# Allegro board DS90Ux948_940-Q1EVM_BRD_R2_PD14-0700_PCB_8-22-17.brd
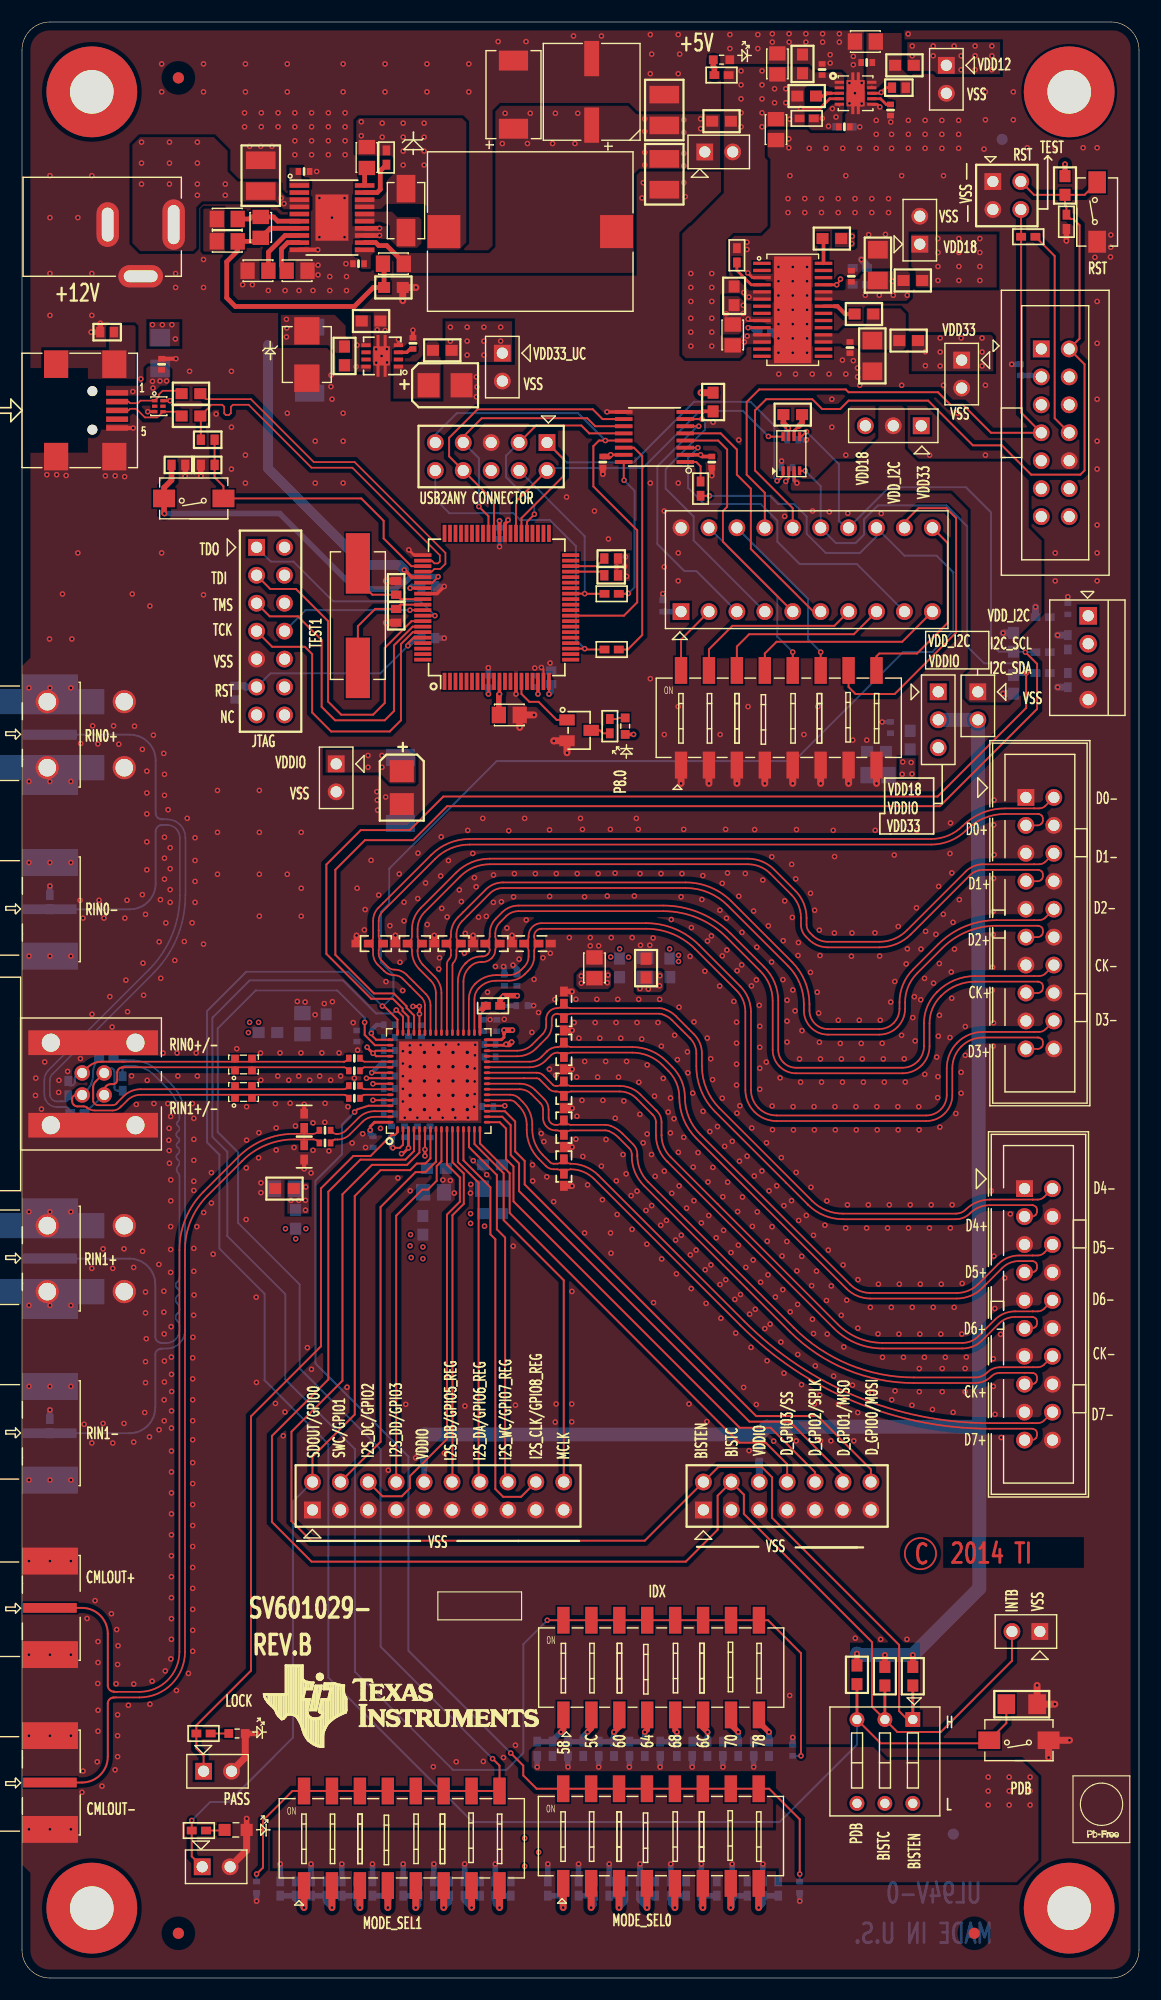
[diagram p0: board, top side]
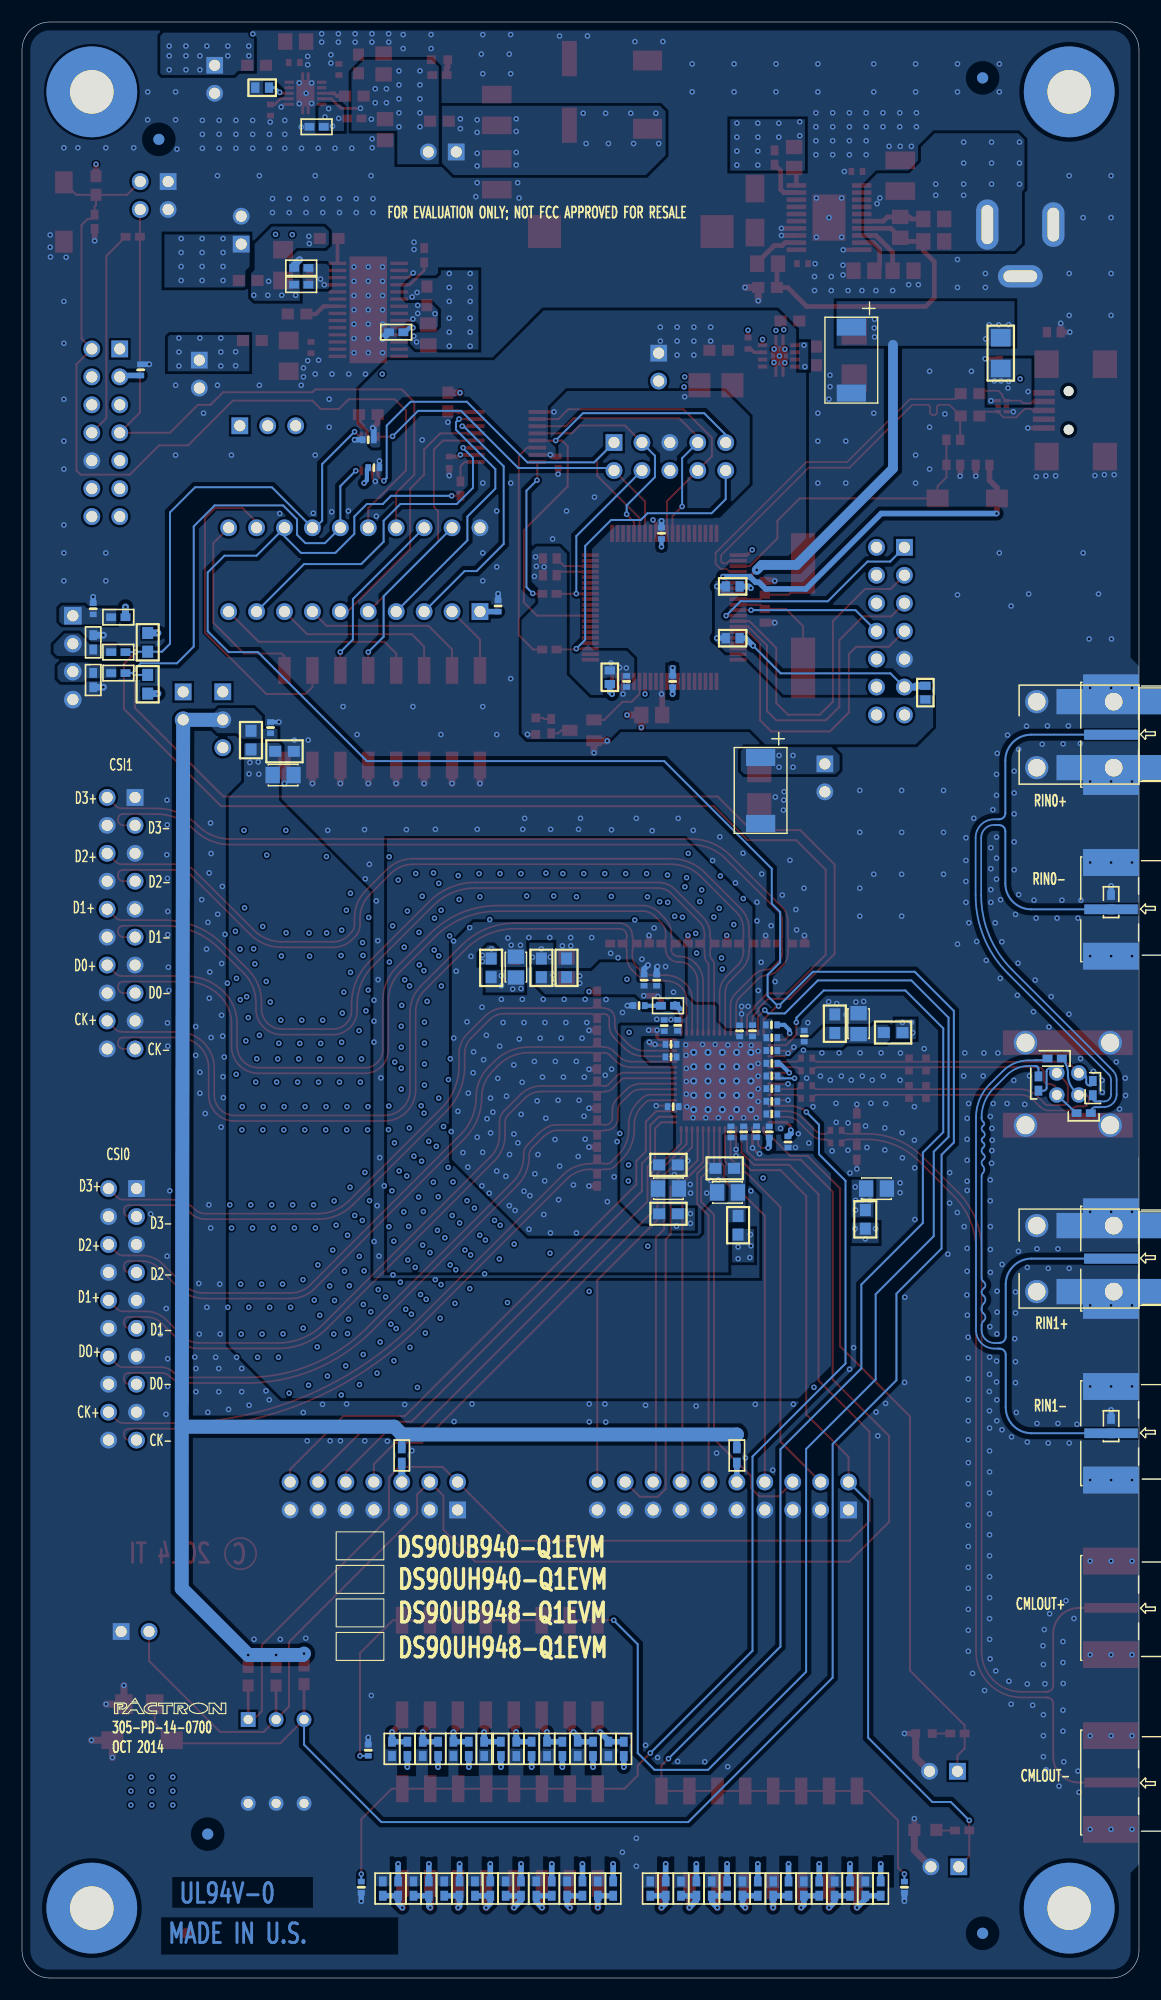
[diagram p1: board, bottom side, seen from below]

Outline 101.6 x 177.8 mm; copper layers: TOP, GND, POWER, BOTTOM. Coordinates in mm from the lower left corner of the outline.
Outline path: 0,175.26 0,2.54 arc(0.74,0.74) 2.54,0 99.06,0 arc(100.86,0.74) 101.6,2.54 101.6,175.26 arc(100.86,177.06) 99.06,177.8 2.54,177.8 arc(0.74,177.06) 0,175.26

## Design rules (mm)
net group DIFFPAIR0: nets N17075556 N17075562
net group DIFFPAIR1: nets RINB+ RINB-
net group DIFFPAIR2: nets RINA+ RINA-
net group DIFFPAIR3: nets N17075712 N17075718
net group DIFFPAIR16: nets N17084985 N17084987
net group DIFFPAIR17: nets N17087573 N17087575
net group DIFFPAIR18: nets DM DP
net group DIFFPAIR19: nets N16849932 N16849953
net group DIFFPAIR20: nets N17103018 N17103031
net group DIFFPAIR21: nets DOUT+ DOUT-

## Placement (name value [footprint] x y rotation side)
C1  0.1uF  [0402_1005_METRIC]  45.47 88.39 180 bottom
C2  0.1uF  [0402_1005_METRIC]  33.43 86.64 180 bottom
C3  0.033uF  [0402_1005_METRIC]  30.23 83.61 0 top
C4  0.033uF  [0402_1005_METRIC]  30.23 82.47 0 top
C5  0.1uF  [0402_1005_METRIC]  33.4 83.14 180 bottom
C6  0.033uF  [0402_1005_METRIC]  30.23 81.11 0 top
C7  0.033uF  [0402_1005_METRIC]  30.23 79.97 0 top
C8  0.1uF  [0402_1005_METRIC]  31.93 76 90 bottom
C9  0.1uF  [0402_1005_METRIC]  27.56 77.06 0 top
C10  0.1uF  [0402_1005_METRIC]  33.63 76.91 270 bottom
C11  0.1uF  [0402_1005_METRIC]  27.56 75.91 0 top
C12  10uF  [1206_3216_METRIC]  90.93 24.89 0 top
C13  2.2uF  [3528-21_EIA]  38.48 144.78 0 top
C14  1uF  [0603_1608_METRIC]  31.75 150.62 0 top
C15  0.01uF  [0402_1005_METRIC]  35.56 148.59 90 top
C16  22uF  [CAP_N]  26.16 147.07 270 bottom
C17  0.1uF  [0402_1005_METRIC]  12.7 146.69 270 top
C18  220PF  [0603]  14.22 137.54 0 top
C19  30pF  [0603]  34.04 123.83 270 top
C20  30pF  [0603]  34.04 126.37 90 top
C21  220PF  [0603]  36.96 126.49 0 bottom
C22  2200PF  [0603]  36.96 121.79 0 bottom
C23  0.1uF  [0402_1005_METRIC]  42.42 117.86 270 bottom
C24  0.1uF  [0402_1005_METRIC]  43.43 131.32 270 bottom
C25  0.1uF  [0402_1005_METRIC]  62.74 137.8 90 top
C26  0.1uF  [0402_1005_METRIC]  52.83 137.8 90 top
C27  0.1uF  [0402_1005_METRIC]  46.61 117.86 270 bottom
C28  4.7uF  [0805_2012_METRIC]  44.32 114.81 0 top
C29  470nF  [0603]  48.13 118.24 90 bottom
C30  0.1uF  [0402_1005_METRIC]  69.6 137.29 0 bottom
C31  0.1uF  [0402_1005_METRIC]  70.1 139.83 180 bottom
C32  0.1uF  [0402_1005_METRIC]  95.12 124.46 90 bottom
C33  4.7pF  [C-0402]  95.12 117.98 270 bottom
C34  4.7pF  [C-0402]  95.12 121.41 90 bottom
C35  0.1uF  [0402_1005_METRIC]  25.65 164.21 0 top
C36  0.022uF  [CAP_HDC-0805_2012_METRIC]  31.37 165.48 90 top
C37  10uF  [1210_3225_METRIC]  21.72 163.83 90 top
C38  100uF  [CAP_7343-31_EIA]  44.7 171.2 90 top
C39  270uF  [CAP_0P327LX0P327W_8P30MMX8P30MM]  51.82 171.45 180 top
C40  100uF  [CAP_HDC-1210_3225_METRIC]  58.42 163.96 270 top
C41  100uF  [CAP_HDC-1210_3225_METRIC]  58.42 169.8 90 top
C42  180pF  [CAP_HDC-0805_2012_METRIC]  21.72 159.13 90 top
C43  150pF  [CAP_HDC-0805_2012_METRIC]  25.02 155.19 0 top
C44  0.01uF  [0402_1005_METRIC]  30.61 155.83 180 top
C45  560pF  [CAP_HDC-0805_2012_METRIC]  18.67 159.89 0 top
C46  4.7uF  [0805_2012_METRIC]  68.71 173.99 90 top
C47  1uF  [0603_1608_METRIC]  70.99 173.99 90 top
C48  0.1uF  [0402_1005_METRIC]  72.77 173.48 90 top
C49  4.7uF  [0805_2012_METRIC]  76.71 176.02 180 top
C50  0.1uF  [0402_1005_METRIC]  76.83 174.12 180 top
C51  0.01uF  [0402_1005_METRIC]  78.99 169.8 270 top
C52  4.7uF  [0805_2012_METRIC]  68.58 168.02 270 top
C53  0.1uF  [0402_1005_METRIC]  74.8 168.28 0 top
C54  10uF  [0805_2012_METRIC]  56.67 91.89 90 bottom
C55  1uF  [0603_1608_METRIC]  56.76 91.8 90 top
C56  0.1uF  [0402_1005_METRIC]  42.57 83.72 180 bottom
C57  0.01uF  [0402_1005_METRIC]  33.4 81.99 0 bottom
C58  0.01uF  [0402_1005_METRIC]  42.57 84.87 180 bottom
C59  10uF  [0805_2012_METRIC]  52.07 91.82 90 top
C60  1uF  [0603_1608_METRIC]  52.07 91.82 90 bottom
C61  0.1uF  [0402_1005_METRIC]  43.87 90.7 90 bottom
C62  0.01uF  [0402_1005_METRIC]  45.02 90.7 90 bottom
C63  4.7uF  [0805_2012_METRIC]  64.64 149.35 90 top
C64  1uF  [0603_1608_METRIC]  64.77 152.91 270 top
C65  0.1uF  [0402_1005_METRIC]  75.44 154.69 270 top
C66  10uF  [1206_3216_METRIC]  77.85 155.7 90 top
C67  10uF  [0805_2012_METRIC]  25.51 86.75 90 bottom
C68  1uF  [0603_1608_METRIC]  27.66 86.75 90 bottom
C69  0.1uF  [0402_1005_METRIC]  30.45 85.62 90 bottom
C70  0.01uF  [0402_1005_METRIC]  33.4 84.3 0 bottom
C71  10uF  [0805_2012_METRIC]  23.88 71.76 180 bottom
C72  1uF  [0603_1608_METRIC]  23.88 71.76 180 top
C73  0.1uF  [0402_1005_METRIC]  33.4 79.7 0 bottom
C74  0.01uF  [0402_1005_METRIC]  33.4 80.85 0 bottom
C75  10uF  [0805_2012_METRIC]  37.44 71.41 0 bottom
C76  1uF  [0603_1608_METRIC]  37.69 73.6 0 bottom
C77  0.1uF  [0402_1005_METRIC]  36.32 86.1 270 bottom
C78  0.01uF  [0402_1005_METRIC]  37.11 76.91 90 bottom
C79  0.1uF  [0402_1005_METRIC]  75.31 148.21 90 top
C80  10uF  [1206_3216_METRIC]  77.34 147.45 270 top
C81  10uF  [0805_2012_METRIC]  42.8 71.76 180 bottom
C82  1uF  [0603_1608_METRIC]  42.8 73.91 180 bottom
C83  0.1uF  [0402_1005_METRIC]  43.19 86.58 90 bottom
C84  0.01uF  [0402_1005_METRIC]  42.37 79.2 180 bottom
C85  0.01uF  [0402_1005_METRIC]  41.97 86.6 90 bottom
C86  0.01uF  [0402_1005_METRIC]  33.4 85.47 0 bottom
C87  0.01uF  [0402_1005_METRIC]  33.4 78.54 0 bottom
C88  22uF  [CAP_N]  34.42 107.95 270 bottom
C89  2.2uF  [3528-21_EIA]  34.54 108.2 270 top
C90  0.1uF  [0402_1005_METRIC]  78.99 113.67 270 bottom
C91  10uF  [0805_2012_METRIC]  77.85 109.35 180 bottom
C92  1uF  [0603_1608_METRIC]  77.72 111.51 180 bottom
C93  0.1uF  [0402_1005_METRIC]  34.79 76.92 90 bottom
C94  0.01uF  [0402_1005_METRIC]  35.96 76.91 90 bottom
C95  0.01uF  [0402_1005_METRIC]  35.15 86.11 270 bottom
C99  0.1uF  [0402_1005_METRIC]  58.29 124.71 270 bottom
C100  0.1uF  [0402_1005_METRIC]  90.81 146.18 270 bottom
C101  2.2nF  [C-0402]  95 159.64 270 top
C102  0.1uF  [0402_1005_METRIC]  70.74 8.26 90 bottom
C103  0.1uF  [0402_1005_METRIC]  21.34 8.26 90 bottom
C104  0.1uF  [0402_1005_METRIC]  70.1 20.7 270 bottom
D1  1SMB5922  [DO-214AA_SMB]  25.91 147.57 90 top
D3  -  [DIODE]  34.92 160.66 270 top
F1  FUSE  [1206]  12.57 147.7 90 bottom
J1  HSD_2X2  [CON_HSD-4P]  -0.13 81.27 90 top
J2  FAKRA  [59S20X-40ML5-Y]  0 113.02 90 bottom
J3  SMA  [EDGE_MOUNT]  0.04 113.02 270 bottom
J4  SMA  [EDGE_MOUNT]  0.04 97.14 270 bottom
J5  SMA  [EDGE_MOUNT]  0.04 33.64 90 top
J6  SMA  [EDGE_MOUNT]  0.04 17.77 90 top
J7  FAKRA  [59S20X-40ML5-Y]  0 65.39 90 bottom
J8  SMA  [EDGE_MOUNT]  0.04 65.39 270 bottom
J9  SMA  [EDGE_MOUNT]  0.04 49.52 270 bottom
J10  mini USB 5pin  [MINI_B_USB_SURFACE_MOUNT]  0 142.49 270 top
J11  HEADER 7X2_open  [0_100INCHX2X7]  21.34 130.05 270 top
J12  HEADER 5X2  [THROUGH_HOLE]  47.75 139.57 180 top
J13  IDC1X4  [IDC-1X4]  96.98 120.02 270 top
J14  HEADER 7X2  [0_100INCHX2X7]  61.98 42.55 0 top
J15  2X10-Pin Header  [N2520_6002RB]  92.58 95.89 270 top
J16  2X10-Pin Header  [N2520_6002RB]  92.46 60.33 270 top
J17  2X10-Pin Header  [HEADER_2X10P]  26.42 42.55 0 top
J18  CONN JACK PWR  [3-TERMINAL_THRU_HOLE_POWER_JACK]  10.79 154.69 180 top
J19  DIP20 SOCKET - MSP430G2403IN20  [DIP-20]  71.37 128.02 0 top
J20  -  [JTAG-14]  93.98 140.46 270 top
J21  2X2-Pin Header  [HEADER_2X2P]  88.31 163.3 270 top
JP1  2-Pin Header_open  [HEADER_2P]  17.79 18.79 0 top
JP2  2-Pin Header_open  [HEADER_2P]  17.66 10.11 0 top
JP3  2-Pin Header_open  [HEADER_2P]  91.31 31.5 180 top
JP4  2-Pin Header  [HEADER_2P]  43.69 146.43 270 top
JP5  3-Pin Header  [HEADER_3P]  79.25 141.1 180 top
JP6  2-Pin Header  [HEADER_2P]  86.94 115.64 270 top
JP7  2-Pin Header  [HEADER_2P]  63.37 165.99 0 top
JP8  2-Pin Header  [HEADER_2P]  84.07 172.59 270 top
JP9  2-Pin Header  [HEADER_2P]  81.66 158.88 90 top
JP10  2-Pin Header  [HEADER_2P]  85.47 145.8 270 top
JP11  2-Pin Header  [HEADER_2P]  28.57 109.09 270 top
JP12  3-Pin Header  [HEADER_3P]  83.34 114.37 270 top
L1  Z = 90 ohm  [L_HDC-0805]  20.15 83.04 0 top
L2  Z = 90 ohm  [L_HDC-0805]  20.15 80.54 0 top
L3  BK1608HS600-T  [L0603]  29.34 147.45 90 top
L4  15uH  [SMD]  46.23 158.75 0 top
L5  FB 1K@100MHz,0603  [L0603_1608_METRIC]  58.93 91.82 270 bottom
L6  FB 120@100MHz,0603  [L0603_1608_METRIC]  54.36 91.82 270 bottom
L7  FB 120@100MHz,0603  [L0603_1608_METRIC]  22.37 85.94 0 bottom
L8  FB 120@100MHz,0603  [L0603_1608_METRIC]  24.89 68.96 90 bottom
L9  FB 120@100MHz,0603  [L0603_1608_METRIC]  36.47 68.43 90 bottom
L10  FB 120@100MHz,0603  [L0603_1608_METRIC]  42.8 69.47 0 bottom
L11  FB 1K@100MHz,0603  [L0603_1608_METRIC]  80.77 112.52 270 bottom
LED1  0603_green_LED  [D-0603]  19.56 22.23 180 top
LED2  0603_orange_LED  [0603_SMT]  19.43 13.46 180 top
LED3  0603_red_LED  [D-0603]  63.63 174.37 180 top
LED4  0603_green_LED  [D-0603]  54.86 113.79 270 top
NOREF  -  []  0 175.26 0 top
NOREF#2  -  [unnamed#2]  95.25 171.45 0 top
NOREF#3  -  []  6.35 6.35 0 top
NOREF#4  -  []  2.54 0 0 top
NOREF#5  -  [unnamed#2]  86.61 4.06 0 top
NOREF#6  -  []  101.6 175.26 0 top
NOREF#7  -  [unnamed#2]  14.22 172.72 0 top
NOREF#8  -  []  0 2.54 0 top
NOREF#9  -  [unnamed#2]  14.22 4.06 0 top
NOREF#10  -  []  2.54 177.8 0 top
NOREF#11  -  []  6.35 171.45 0 top
NOREF#12  -  []  95.25 6.35 0 top
NOREF#13  -  []  95.25 171.45 0 top
NOREF#14  -  []  95.25 6.35 0 top
NOREF#15  -  []  99.06 0 0 top
NOREF#16  -  [unnamed#2]  6.35 6.35 0 top
NOREF#17  -  []  6.35 6.35 0 top
NOREF#18  -  []  6.35 171.45 0 top
NOREF#19  -  [unnamed#2]  95.25 6.35 0 top
NOREF#20  -  []  101.6 2.54 0 top
NOREF#21  -  []  95.25 171.45 0 top
NOREF#22  -  [unnamed#2]  6.35 171.45 0 top
NOREF#23  -  []  99.06 177.8 0 top
NOREF#24  -  [unnamed#2]  14.22 4.06 180 bottom
NOREF#25  -  [unnamed#2]  89.15 167.13 180 bottom
NOREF#26  -  [unnamed#2]  84.71 13.08 180 bottom
NOREF#27  -  [unnamed#2]  14.22 172.72 180 bottom
Q1  BSS138  [SOT23]  50.67 113.41 270 top
R1  220 Ohm,0402  [RES_HDC-0402]  16.51 22.23 180 top
R2  220 Ohm,0402  [RES_HDC-0402]  16.09 13.41 180 top
R3  0 Ohm,0402_open  [RES_HDC-0402]  42.84 88.38 180 top
R4  0 Ohm,0402  [RES_HDC-0402]  42.84 88.38 0 bottom
R5  45.3K Ohm,0402  [RES_HDC-0402]  67.39 8.13 270 bottom
R6  90.9K Ohm,0402  [RES_HDC-0402]  64.59 8.13 270 bottom
R7  107K Ohm,0402  [RES_HDC-0402]  61.8 8.13 270 bottom
R8  113K Ohm,0402  [RES_HDC-0402]  59 8.13 270 bottom
R9  113K Ohm,0402  [RES_HDC-0402]  56.21 8.13 270 bottom
R10  107K Ohm,0402  [RES_HDC-0402]  53.42 8.13 270 bottom
R11  232K Ohm,0402  [RES_HDC-0402]  50.62 8.13 270 bottom
R12  0 Ohm,0402_open  [RES_HDC-0402]  47.83 8.13 270 bottom
R13  45.3K Ohm,0402  [RES_HDC-0402]  43.05 8.13 270 bottom
R14  90.9K Ohm,0402  [RES_HDC-0402]  40.26 8.13 270 bottom
R15  107K Ohm,0402  [RES_HDC-0402]  37.46 8.13 270 bottom
R16  113K Ohm,0402  [RES_HDC-0402]  34.67 8.13 270 bottom
R17  113K Ohm,0402  [RES_HDC-0402]  31.88 8.13 270 bottom
R18  107K Ohm,0402  [RES_HDC-0402]  29.08 8.13 270 bottom
R19  232K Ohm,0402  [RES_HDC-0402]  26.29 8.13 270 bottom
R20  0 Ohm,0402_open  [RES_HDC-0402]  23.49 8.13 270 bottom
R21  182K Ohm,0402  [RES_HDC-0402]  68.78 8.13 90 bottom
R22  113K Ohm,0402  [RES_HDC-0402]  65.99 8.13 90 bottom
R23  93.1K Ohm,0402  [RES_HDC-0402]  63.2 8.13 90 bottom
R24  68.1K Ohm,0402  [RES_HDC-0402]  60.4 8.13 90 bottom
R25  47.5K Ohm,0402  [RES_HDC-0402]  57.61 8.13 90 bottom
R26  31.6K Ohm,0402  [RES_HDC-0402]  54.81 8.13 90 bottom
R27  47.5K Ohm,0402  [RES_HDC-0402]  52.02 8.13 90 bottom
R28  40.2K Ohm,0402  [RES_HDC-0402]  49.23 8.13 90 bottom
R29  182K Ohm,0402  [RES_HDC-0402]  44.45 8.13 90 bottom
R30  113K Ohm,0402  [RES_HDC-0402]  41.66 8.13 90 bottom
R31  93.1K Ohm,0402  [RES_HDC-0402]  38.86 8.13 90 bottom
R32  68.1K Ohm,0402  [RES_HDC-0402]  36.07 8.13 90 bottom
R33  47.5K Ohm,0402  [RES_HDC-0402]  33.27 8.13 90 bottom
R34  31.6K Ohm,0402  [RES_HDC-0402]  30.48 8.13 90 bottom
R35  47.5K Ohm,0402  [RES_HDC-0402]  27.69 8.13 90 bottom
R36  40.2K Ohm,0402  [RES_HDC-0402]  24.89 8.13 90 bottom
R37  0 Ohm,0402_open  [RES_HDC-0402]  4.2 80.89 90 bottom
R38  0 Ohm,0402_open  [RES_HDC-0402]  5.03 78.62 0 bottom
R40  45.3K Ohm,0402  [RES_HDC-0402]  66.55 20.83 90 bottom
R41  90.9K Ohm,0402  [RES_HDC-0402]  63.75 20.83 90 bottom
R42  107K Ohm,0402  [RES_HDC-0402]  60.96 20.83 90 bottom
R43  113K Ohm,0402  [RES_HDC-0402]  58.04 20.83 90 bottom
R44  113K Ohm,0402  [RES_HDC-0402]  55.24 20.83 90 bottom
R45  107K Ohm,0402  [RES_HDC-0402]  52.45 20.83 90 bottom
R46  232K Ohm,0402  [RES_HDC-0402]  49.66 20.83 90 bottom
R47  0 Ohm,0402_open  [RES_HDC-0402]  46.86 20.83 90 bottom
R48  49.9ohm,0402_open  [RES_HDC-0402]  25.67 77.92 90 top
R49  49.9ohm,0402_open  [RES_HDC-0402]  25.67 75.05 270 top
R50  49.9ohm,0402_open  [RES_HDC-0402]  2.54 97.79 90 bottom
R52  182K Ohm,0402  [RES_HDC-0402]  67.94 20.83 270 bottom
R53  113K Ohm,0402  [RES_HDC-0402]  65.15 20.83 270 bottom
R54  93.1K Ohm,0402  [RES_HDC-0402]  62.36 20.83 270 bottom
R55  68.1K Ohm,0402  [RES_HDC-0402]  59.56 20.83 270 bottom
R56  47.5K Ohm,0402  [RES_HDC-0402]  56.64 20.83 270 bottom
R57  31.6K Ohm,0402  [RES_HDC-0402]  53.85 20.83 270 bottom
R58  47.5K Ohm,0402  [RES_HDC-0402]  51.05 20.83 270 bottom
R59  40.2K Ohm,0402  [RES_HDC-0402]  48.26 20.83 270 bottom
R60  10K  [RES_HDC-0603]  75.95 27.56 90 top
R61  10K  [RES_HDC-0603]  78.49 27.43 90 top
R62  10K  [RES_HDC-0603]  81.03 27.43 90 top
R63  0 Ohm,0402_open  [RES_HDC-0402]  9.14 81.31 270 bottom
R64  0 Ohm,0402_open  [RES_HDC-0402]  7.67 83.59 180 bottom
R65  49.9ohm,0402_open  [RES_HDC-0402]  2.54 50.17 90 bottom
R66  33 ohm  [RES_0603]  15.37 144.02 0 top
R67  33 ohm  [RES_0603]  15.37 141.99 0 top
R68  0 Ohm, 0603  [R0603_1608_METRIC]  38.23 147.96 180 top
R69  1.5K  [0603]  16.89 139.83 0 top
R70  33K ohm  [0603]  7.75 149.61 180 top
R71  1.2M ohm  [0603]  16.89 137.54 180 top
R72  33K ohm  [0603]  19.43 116.84 270 bottom
R73  0 Ohm,0402_open  [RES_HDC-0402]  53.63 125.82 0 top
R74  0 Ohm,0402_open  [RES_HDC-0402]  53.63 120.76 0 top
R75  220 Ohm,0402  [RES_HDC-0402]  53.47 113.79 270 top
R76  10K  [RES_HDC-0603]  62.86 143.26 90 top
R77  10K  [RES_HDC-0603]  70.1 142.11 0 top
R78  1.5K  [0603]  53.59 127.51 0 top
R79  1.5K  [0603]  53.59 129.03 0 top
R80  100_open  [RES_HDC-0402]  32.19 94.03 0 top
R81  4.7K  [R-0603]  90.17 117.6 90 bottom
R82  4.7K  [R-0603]  90.17 121.41 270 bottom
R83  0 Ohm  [R-0402]  92.84 123.7 180 bottom
R84  0 Ohm  [R-0402]  92.84 118.62 0 bottom
R85  0 Ohm  [R-0402]  92.84 120.52 0 bottom
R86  100_open  [RES_HDC-0402]  35.73 94.03 0 top
R87  0 Ohm,0402_open  [RES_HDC-0402]  67.06 47.5 90 bottom
R88  100_open  [RES_HDC-0402]  39.26 94.03 0 top
R89  100_open  [RES_HDC-0402]  42.8 94.03 0 top
R90  100_open  [RES_HDC-0402]  46.33 94.03 0 top
R91  0 Ohm,0402_open  [RES_HDC-0402]  36.58 47.5 90 bottom
R92  100_open  [RES_HDC-0402]  49.29 87.91 270 top
R93  100_open  [RES_HDC-0402]  49.29 84.37 270 top
R94  100_open  [RES_HDC-0402]  49.29 80.84 270 top
R95  100_open  [RES_HDC-0402]  49.29 77.3 270 top
R96  100_open  [RES_HDC-0402]  49.29 73.77 270 top
R97  0 Ohm,0402  [RES_HDC-0402]  33.15 165.48 270 top
R98  220 Ohm,0402  [RES_HDC-0402]  63.63 172.97 0 top
R99  0 Ohm, 0603  [R0603_1608_METRIC]  63.63 168.78 0 top
R100  52.3Kohm  [RES_HDC-0805_2012_METRIC]  18.67 157.86 180 top
R101  9.53Kohm  [RES_HDC-0805_2012_METRIC]  21.46 155.19 180 top
R102  3.09Kohm  [RES_HDC-0805_2012_METRIC]  33.78 155.83 180 top
R103  0 Ohm, 0603  [R0603_1608_METRIC]  80.26 173.86 0 top
R104  2.49K  [0603]  79.76 171.83 0 top
R105  100K  [RES_HDC-0603]  71.37 171.07 180 top
R106  1K  [RES_HDC-0603]  33.78 153.67 180 top
R107  0 Ohm,0402  [RES_HDC-0402]  71.37 169.04 0 top
R108  4.99K  [0603]  79.76 171.83 180 bottom
R109  0 Ohm,0402_open  [RES_HDC-0402]  74.8 168.28 0 bottom
R110  23.2K  [0402]  76.2 155.45 180 bottom
R111  100K  [RES_HDC-0603]  73.66 158.12 180 top
R112  12.1K  [0402]  76.2 153.92 180 bottom
R113  0 Ohm, 0603  [R0603_1608_METRIC]  81.03 154.31 0 top
R114  100K  [RES_HDC-0603]  76.58 151.26 180 top
R115  0 Ohm,0402  [RES_HDC-0402]  65.02 156.59 270 top
R116  0 Ohm,0402  [RES_HDC-0402]  67.56 149.61 180 bottom
R117  0 Ohm, 0603  [R0603_1608_METRIC]  80.64 148.84 0 top
R118  330ohm  [R-0402]  91.53 158.28 180 top
R119  47Kohm  [R-0603]  94.87 162.94 90 top
R120  0 Ohm,0402_open  [RES_HDC-0402]  61.72 135.38 90 top
S1  SW SMD-8  [SMD-20]  58.12 12.9 0 top
S2  SW SMD-8  [SMD-20]  34.54 12.7 0 top
S3  SW DIP-3  [DIP-6]  78.49 19.69 180 top
S4  SW SMD-8  [SMD-20]  58.14 28.22 0 top
S5  SW SMD-8  [SMD-20]  68.83 114.55 0 top
SW1  SPST  [ADTSM31NV]  90.68 21.61 180 top
SW2  SPST  [ADTSM31NV]  15.62 134.49 180 top
SW3  SPST  [ADTSM31NV]  97.79 160.53 90 top
TP1  TEST POINT  [TEST_POINT]  33.96 94.03 0 top
TP2  TEST POINT  [TEST_POINT]  30.42 94.03 0 top
TP3  TEST POINT  [TEST_POINT]  37.49 94.03 0 top
TP4  TEST POINT  [TEST_POINT]  41.03 94.03 0 top
TP5  TEST POINT  [TEST_POINT]  48.1 94.03 0 top
TP6  TEST POINT  [TEST_POINT]  44.56 94.03 0 top
TP7  TEST POINT  [TEST_POINT]  49.29 79.07 90 top
TP8  TEST POINT  [TEST_POINT]  49.29 82.6 90 top
TP9  TEST POINT  [TEST_POINT]  49.29 75.53 90 top
TP10  TEST POINT  [TEST_POINT]  49.29 86.14 90 top
TP11  TEST POINT  [TEST_POINT]  49.29 72 90 top
TP12  TEST POINT  [TEST_POINT]  49.29 89.67 90 top
U1  DS90UH948Q  [WQFN-64]  37.9 81.54 90 top
U2  TPS73533DRB  [TPS73533DRBT]  32.77 147.45 90 top
U3  TPD4E004DRY  [SON-6]  12.45 142.88 270 top
U4  MSP430F5529IPN  [TQFP-80]  43.18 124.59 0 top
U5  TXB0106IPWR  [16TSSOP]  57.53 140.08 90 top
U6  TCA9406DCUR  [8-VFSOP_0P091_2P30MM_WIDTH]  69.98 138.56 90 top
U7  LM25576MH/NOPB  [20-TSSOP]  28.19 160.02 270 top
U8  TPS74801DRC  [10-VFDFN_EXPOSED_PAD]  75.82 171.32 0 top
U9  TPS767D318PWP  [28-HTSSOP]  70.1 151.64 270 top
Y1  Crystal, SMT Quart Crystal  [0_484X0_190_INCH]  30.55 123.84 270 top

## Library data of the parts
C1 C2 C5 C8 C10 C24 C28 C32 C46 C48-C50 C52-C54 C56 C59 C61 C63 C65 C67 C69 C71 C73 C75 C77 C79 C81 C83 C90 C91 C93 C102-C104 = CAPACITOR NON-POL_12
C3 C4 C6 C7 C9 C11 C17 C23 C25-C27 C30 C31 C35 C99 C100 = CAPACITOR NON-POL_0
C12 C66 C80 = CAPACITOR NON-POL_9
C13 C16 C38 C39 C88 C89 = CAPACITOR POL_1
C14 C47 C55 C60 C64 C68 C72 C76 C82 C92 = CAPACITOR NON-POL_10
C15 C40 C41 C44 C51 C57 C58 C62 C70 C74 C78 C84-C87 C94 C95 = CAPACITOR NON-POL_11
C18 C21 C22 = CAP NP
C19 C20 C29 = C
C33 C34 = CAPACITOR NON-POL_3
C36 C37 C42 C43 C45 = CAPACITOR NON-POL_5
C101 = CAPACITOR NON-POL_7
D1 = DIODE_ZENER
D3 = DIODE_2
F1 = FUSE
J1 = Automotive HSD Connector 2X2_4
J2-J9 = CON5_5
J10 = mini B USB 5pin_5
J11 J14 = HEADER 7X2
J12 = HEADER 5X2
J13 = IDC_1 x 4_2
J15 J16 = JUMPER_14
J17 = JUMPER_1
J18 = CONN JACK PWR
J19 = DIP8 SOCKET_4
J20 = DIP8 SOCKET_5
J21 = JUMPER_20
JP1 JP2 = JUMPER_17
JP3 JP4 JP6-JP11 = JUMPER_0
JP5 JP12 = JUMPER_13
L1 L2 = DLW21S Series_1
L3 = INDUCTOR_1
L4-L11 = INDUCTOR
LED1-LED4 = LED LTST-C230JAKT_2
Q1 = NDS355N/SOT
R1-R38 R40-R50 R52-R59 R63-R65 R73-R75 R87 R91 R97 R98 R107 R109 R115 R116 R120 = R_6
R60-R62 R76 R77 R100-R102 R104-R106 R108 R110-R112 R114 = R_7
R66 R67 R69-R72 R78 R79 = R
R68 R99 R103 R113 R117 = R_1
R80 R86 R88-R90 R92-R96 = 0201 size pads_2
R81 R82 = R_2
R83-R85 = R_3
R118 R119 = ERJ-1GE0R00C_2
S1 S2 S4 S5 = SW SMD-8_1
S3 = SW DIP-8_19
SW1-SW3 = SW PUSHBUTTON-SPST
TP1-TP12 = TEST POINT
U1 = DS90UH928Q_3
U2 = LP3982IMM-ADJ_2
U3 = TPD4E004DRY
U4 = MSP430F5529IPN_0
U5 = CD40109BMS_1
U6 = PCA9306_0
U7 = PKG_20_TSSOP_EP_0
U8 = TPS62052_MSOP_3
U9 = LM2640_SO_8
Y1 = CRYSTAL

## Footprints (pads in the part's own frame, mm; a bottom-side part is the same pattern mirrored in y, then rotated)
0_100INCHX2X7
  rect 1.524x1.524 hole 1.016: 1(0,0)
  round 1.524 hole 1.016: 2(0,2.54) 3(2.54,0) 4(2.54,2.54) 5(5.08,0) 6(5.08,2.54) 7(7.62,0) 8(7.62,2.54) 9(10.16,0) 10(10.16,2.54) 11(12.7,0) 12(12.7,2.54) 13(15.24,0) 14(15.24,2.54)
0_484X0_190_INCH
  rect 5.5x2.2 smd: 1(-4.75,0) 2(4.75,0)
3-TERMINAL_THRU_HOLE_POWER_JACK
  oval 2.032x4.572 hole 1.067x3.556: 1(-3,-4.7)
  oval 2.032x4.064 hole 1.067x3.073: 2(3,-4.7)
  oval 4.064x2.032 hole 3.073x1.067: 3(0,0)
8-VFSOP_0P091_2P30MM_WIDTH
  rect 0.813x0.305 smd: 1(-1.551,0.75) 2(-1.551,0.25) 3(-1.551,-0.25) 4(-1.551,-0.75) 5(1.551,-0.75) 6(1.551,-0.25) 7(1.551,0.25) 8(1.551,0.75)
10-VFDFN_EXPOSED_PAD
  rect 0.85x0.28 smd: 1(-1.475,1) 2(-1.475,0.5) 3(-1.475,0) 4(-1.475,-0.5) 5(-1.475,-1) 6(1.475,-1) 7(1.475,-0.5) 8(1.475,0) 9(1.475,0.5) 10(1.475,1)
  custom 0.412x0.412 smd: 11(0,0)
16TSSOP
  rect 0.35x1.6 smd: 1(-2.275,-2.8) 2(-1.625,-2.8) 3(-0.975,-2.8) 4(-0.325,-2.8) 5(0.325,-2.8) 6(0.975,-2.8) 7(1.625,-2.8) 8(2.275,-2.8) 9(2.275,2.8) 10(1.625,2.8) 11(0.975,2.8) 12(0.325,2.8) 13(-0.325,2.8) 14(-0.975,2.8) 15(-1.625,2.8) 16(-2.275,2.8)
20-TSSOP
  rect 0.42x1.78 smd: 1(-2.925,-2.97) 2(-2.275,-2.97) 3(-1.625,-2.97) 4(-0.975,-2.97) 5(-0.325,-2.97) 6(0.325,-2.97) 7(0.975,-2.97) 8(1.625,-2.97) 9(2.275,-2.97) 10(2.925,-2.97) 11(2.925,2.97) 12(2.275,2.97) 13(1.625,2.97) 14(0.975,2.97) 15(0.325,2.97) 16(-0.325,2.97) 17(-0.975,2.97) 18(-1.625,2.97) 19(-2.275,2.97) 20(-2.925,2.97)
  rect 4.2x3 smd: 21(0,0)
28-HTSSOP
  rect 0.3x1.6 smd: 1(-4.225,-2.8) 2(-3.575,-2.8) 3(-2.925,-2.8) 4(-2.275,-2.8) 5(-1.625,-2.8) 6(-0.975,-2.8) 7(-0.325,-2.8) 8(0.325,-2.8) 9(0.975,-2.8) 10(1.625,-2.8) 11(2.275,-2.8) 12(2.925,-2.8) 13(3.575,-2.8) 14(4.225,-2.8) 15(4.225,2.8) 16(3.575,2.8) 17(2.925,2.8) 18(2.275,2.8) 19(1.625,2.8) 20(0.975,2.8) 21(0.325,2.8) 22(-0.325,2.8) 23(-0.975,2.8) 24(-1.625,2.8) 25(-2.275,2.8) 26(-2.925,2.8) 27(-3.575,2.8) 28(-4.225,2.8)
  rect 9.7x3.4 smd: 29(0,0)
59S20X-40ML5-Y
  rect 0.889x4.877 smd: 1(0,2.538)
  round 2.108 hole 1.6: 2(-3,2.3) 3(3,2.3) 4(3,9.3) 5(-3,9.3)
0402
  rect 0.9x0.7 smd: 1(-0.65,0) 2(0.65,0)
0402_1005_METRIC
  rect 0.508x0.635 smd: 1(-0.508,0) 2(0.508,0)
0603
  rect 0.75x0.95 smd: 1(-0.625,0) 2(0.625,0)
0603_1608_METRIC
  rect 1.1x1 smd: 1(-0.85,0) 2(0.85,0)
0603_SMT
  rect 1.1x1.1 smd: 1(-1,0) 2(1,0)
0805_2012_METRIC
  rect 1.3x1.5 smd: 1(-0.95,0) 2(0.95,0)
1206
  rect 1.6x1.8 smd: 1(-1.4,0) 2(1.4,0)
1206_3216_METRIC
  rect 1.6x1.8 smd: 1(-1.4,0) 2(1.4,0)
1210_3225_METRIC
  rect 1.6x2.7 smd: 1(-1.4,0) 2(1.4,0)
3528-21_EIA
  rect 2x2.2 smd: 1(-1.5,0) 2(1.5,0)
ADTSM31NV
  rect 2x1.6 smd: 1(-2.7,0) 2(2.7,0)
C-0402
  rect 0.9x0.7 smd: 1(-0.65,0) 2(0.65,0)
CAP_0P327LX0P327W_8P30MMX8P30MM
  rect 1.354x3.204 smd: 1(0,3.025) 2(0,-3.025)
CAP_7343-31_EIA
  rect 1.808x2.654 smd: 1(-3.1,0) 2(3.1,0)
CAP_HDC-0805_2012_METRIC
  rect 1.3x1.5 smd: 1(-0.95,0) 2(0.95,0)
CAP_HDC-1210_3225_METRIC
  rect 1.6x2.7 smd: 1(-1.4,0) 2(1.4,0)
CAP_N
  rect 1.554x2.654 smd: 1(-3,0) 2(3,0)
CON_HSD-4P
  round 1.4 hole 0.9: 1(1,-7.6) 2(1,-5.6) 3(-1,-5.6) 4(-1,-7.6)
  rect 2.25x11.8 hole 1.65: 5(-3.75,-10.45) 6(3.75,-10.45)
  round 2.158 hole 1.65: 7(3.75,-2.75) 8(-3.75,-2.75)
D-0603
  rect 0.8x0.8 smd: 1(-0.75,0) 2(0.75,0)
DIODE
  rect 2.5x1.7 smd: 1(-2,0) 2(2,0)
DIP-6
  rect 1.346x1.346 hole 0.838: 1(-2.54,-3.81)
  round 1.346 hole 0.838: 2(0,-3.81) 3(2.54,-3.81) 4(2.54,3.81) 5(0,3.81) 6(-2.54,3.81)
DIP-20
  rect 1.524x1.524 hole 1.016: 1(-11.43,-3.81)
  round 1.524 hole 1.016: 2(-8.89,-3.81) 3(-6.35,-3.81) 4(-3.81,-3.81) 5(-1.27,-3.81) 6(1.27,-3.81) 7(3.81,-3.81) 8(6.35,-3.81) 9(8.89,-3.81) 10(11.43,-3.81) 11(11.43,3.81) 12(8.89,3.81) 13(6.35,3.81) 14(3.81,3.81) 15(1.27,3.81) 16(-1.27,3.81) 17(-3.81,3.81) 18(-6.35,3.81) 19(-8.89,3.81) 20(-11.43,3.81)
DO-214AA_SMB
  rect 2.5x2.3 smd: 1(-2.15,0) 2(2.15,0)
EDGE_MOUNT
  rect 0.889x4.877 smd: 1(0,-2.502)
  rect 2.413x5.08 smd: 2(-4.255,-2.502) 3(4.255,-2.502) 4(4.255,-2.502) 5(-4.255,-2.502)
HEADER_2P
  rect 1.524x1.524 hole 1.016: 1(-1.27,0)
  round 1.524 hole 1.016: 2(1.27,0)
HEADER_2X2P
  rect 1.524x1.524 hole 1.016: 1(0,0)
  round 1.524 hole 1.016: 2(0,2.54) 3(2.54,0) 4(2.54,2.54)
HEADER_2X10P
  rect 1.524x1.524 hole 1.016: 1(0,0)
  round 1.524 hole 1.016: 2(0,2.54) 3(2.54,0) 4(2.54,2.54) 5(5.08,0) 6(5.08,2.54) 7(7.62,0) 8(7.62,2.54) 9(10.16,0) 10(10.16,2.54) 11(12.7,0) 12(12.7,2.54) 13(15.24,0) 14(15.24,2.54) 15(17.78,0) 16(17.78,2.54) 17(20.32,0) 18(20.32,2.54) 19(22.86,0) 20(22.86,2.54)
HEADER_3P
  rect 1.524x1.524 hole 1.016: 1(-2.54,0)
  round 1.524 hole 1.016: 2(0,0) 3(2.54,0)
IDC-1X4
  rect 1.6x1.6 hole 1.016: 1(-3.81,0)
  round 1.6 hole 1.016: 2(-1.27,0) 3(1.27,0) 4(3.81,0)
JTAG-14
  rect 1.524x1.524 hole 1.016: 1(-7.62,-1.27)
  round 1.524 hole 1.016: 2(-7.62,1.27) 3(-5.08,-1.27) 4(-5.08,1.27) 5(-2.54,-1.27) 6(-2.54,1.27) 7(0,-1.27) 8(0,1.27) 9(2.54,-1.27) 10(2.54,1.27) 11(5.08,-1.27) 12(5.08,1.27) 13(7.62,-1.27) 14(7.62,1.27)
L0603
  rect 1.1x1 smd: 1(-0.85,0) 2(0.85,0)
L0603_1608_METRIC
  rect 1.1x1 smd: 1(-0.85,0) 2(0.85,0)
L_HDC-0805
  rect 0.704x0.704 smd: 1(-0.775,-0.552) 2(0.775,-0.552) 3(0.775,0.552) 4(-0.775,0.552)
MINI_B_USB_SURFACE_MOUNT
  round 0.9 hole 0.9 unplated: (-1.75,6.401) (1.75,6.401)
  rect 0.5x2 smd: 1(-1.6,8.651) 2(-0.8,8.651) 3(0,8.651) 4(0.8,8.651) 5(1.6,8.651)
  rect 2.5x2.2 smd: 6(-4.2,8.4) 7(-4.2,3.101) 8(4.2,3.101) 9(4.2,8.4)
N2520_6002RB
  rect 1.524x1.524 hole 1.016: 1(-11.43,-1.27)
  round 1.524 hole 1.016: 2(-11.43,1.27) 3(-8.89,-1.27) 4(-8.89,1.27) 5(-6.35,-1.27) 6(-6.35,1.27) 7(-3.81,-1.27) 8(-3.81,1.27) 9(-1.27,-1.27) 10(-1.27,1.27) 11(1.27,-1.27) 12(1.27,1.27) 13(3.81,-1.27) 14(3.81,1.27) 15(6.35,-1.27) 16(6.35,1.27) 17(8.89,-1.27) 18(8.89,1.27) 19(11.43,-1.27) 20(11.43,1.27)
R0603_1608_METRIC
  rect 1.1x1 smd: 1(-0.85,0) 2(0.85,0)
R-0402
  rect 0.9x0.7 smd: 1(-0.65,0) 2(0.65,0)
R-0603
  rect 1.1x1 smd: 1(-0.85,0) 2(0.85,0)
RES_0603
  rect 1.1x1 smd: 1(-0.85,0) 2(0.85,0)
RES_HDC-0402
  rect 0.9x0.7 smd: 1(-0.65,0) 2(0.65,0)
RES_HDC-0603
  rect 1.1x1 smd: 1(-0.85,0) 2(0.85,0)
RES_HDC-0805_2012_METRIC
  rect 1.3x1.5 smd: 1(-0.95,0) 2(0.95,0)
SMD
  rect 3x3 smd: 1(-7.85,0) 2(7.85,0)
SMD-20
  rect 1.13x2.44 smd: 1(-8.89,-4.3) 2(-8.89,4.3) 3(-6.35,-4.3) 4(-6.35,4.3) 5(-3.81,-4.3) 6(-3.81,4.3) 7(-1.27,-4.3) 8(-1.27,4.3) 9(1.27,-4.3) 10(1.27,4.3) 11(3.81,-4.3) 12(3.81,4.3) 13(6.35,-4.3) 14(6.35,4.3) 15(8.89,-4.3) 16(8.89,4.3)
SON-6
  rect 0.3x0.52 smd: 1(-0.5,-0.38)
  rect 0.3x0.49 smd: 2(0,-0.375) 3(0.5,-0.375) 4(0.5,0.375) 5(0,0.375) 6(-0.5,0.375)
SOT23
  rect 1x1.4 smd: 1(-0.95,-1.1) 2(0.95,-1.1) 3(0,1.1)
TEST_POINT
  rect 0.9x0.7 smd: 1(0,0)
THROUGH_HOLE
  rect 1.524x1.524 hole 1.016: 1(0,0)
  round 1.524 hole 1.016: 2(0,2.54) 3(2.54,0) 4(2.54,2.54) 5(5.08,0) 6(5.08,2.54) 7(7.62,0) 8(7.62,2.54) 9(10.16,0) 10(10.16,2.54)
TPS73533DRBT
  rect 0.35x0.85 smd: 1(-0.975,-1.475) 2(-0.325,-1.475) 3(0.325,-1.475) 4(0.975,-1.475) 5(0.975,1.475) 6(0.325,1.475) 7(-0.325,1.475) 8(-0.975,1.475)
  custom 0.375x0.375 smd: 9(0,0.06)
TQFP-80
  rect 0.34x1.56 smd: 1(-4.75,-6.725) 2(-4.25,-6.725) 3(-3.75,-6.725) 4(-3.25,-6.725) 5(-2.75,-6.725) 6(-2.25,-6.725) 7(-1.75,-6.725) 8(-1.25,-6.725) 9(-0.75,-6.725) 10(-0.25,-6.725) 11(0.25,-6.725) 12(0.75,-6.725) 13(1.25,-6.725) 14(1.75,-6.725) 15(2.25,-6.725) 16(2.75,-6.725) 17(3.25,-6.725) 18(3.75,-6.725) 19(4.25,-6.725) 20(4.75,-6.725) 41(4.75,6.725) 42(4.25,6.725) 43(3.75,6.725) 44(3.25,6.725) 45(2.75,6.725) 46(2.25,6.725) 47(1.75,6.725) 48(1.25,6.725) 49(0.75,6.725) 50(0.25,6.725) 51(-0.25,6.725) 52(-0.75,6.725) 53(-1.25,6.725) 54(-1.75,6.725) 55(-2.25,6.725) 56(-2.75,6.725) 57(-3.25,6.725) 58(-3.75,6.725) 59(-4.25,6.725) 60(-4.75,6.725)
  rect 1.56x0.34 smd: 21(6.725,-4.75) 22(6.725,-4.25) 23(6.725,-3.75) 24(6.725,-3.25) 25(6.725,-2.75) 26(6.725,-2.25) 27(6.725,-1.75) 28(6.725,-1.25) 29(6.725,-0.75) 30(6.725,-0.25) 31(6.725,0.25) 32(6.725,0.75) 33(6.725,1.25) 34(6.725,1.75) 35(6.725,2.25) 36(6.725,2.75) 37(6.725,3.25) 38(6.725,3.75) 39(6.725,4.25) 40(6.725,4.75) 61(-6.725,4.75) 62(-6.725,4.25) 63(-6.725,3.75) 64(-6.725,3.25) 65(-6.725,2.75) 66(-6.725,2.25) 67(-6.725,1.75) 68(-6.725,1.25) 69(-6.725,0.75) 70(-6.725,0.25) 71(-6.725,-0.25) 72(-6.725,-0.75) 73(-6.725,-1.25) 74(-6.725,-1.75) 75(-6.725,-2.25) 76(-6.725,-2.75) 77(-6.725,-3.25) 78(-6.725,-3.75) 79(-6.725,-4.25) 80(-6.725,-4.75)
unnamed#2
  round 8.255 hole 3.962 unplated: (0,0)
WQFN-64
  oval 0.6x0.25 smd: 1(-4.4,3.75) 2(-4.4,3.25) 3(-4.4,2.75) 4(-4.4,2.25) 5(-4.4,1.75) 6(-4.4,1.25) 7(-4.4,0.75) 8(-4.4,0.25) 9(-4.4,-0.25) 10(-4.4,-0.75) 11(-4.4,-1.25) 12(-4.4,-1.75) 13(-4.4,-2.25) 14(-4.4,-2.75) 15(-4.4,-3.25) 16(-4.4,-3.75) 33(4.4,-3.75) 34(4.4,-3.25) 35(4.4,-2.75) 36(4.4,-2.25) 37(4.4,-1.75) 38(4.4,-1.25) 39(4.4,-0.75) 40(4.4,-0.25) 41(4.4,0.25) 42(4.4,0.75) 43(4.4,1.25) 44(4.4,1.75) 45(4.4,2.25) 46(4.4,2.75) 47(4.4,3.25) 48(4.4,3.75)
  oval 0.25x0.6 smd: 17(-3.75,-4.4) 18(-3.25,-4.4) 19(-2.75,-4.4) 20(-2.25,-4.4) 21(-1.75,-4.4) 22(-1.25,-4.4) 23(-0.75,-4.4) 24(-0.25,-4.4) 25(0.25,-4.4) 26(0.75,-4.4) 27(1.25,-4.4) 28(1.75,-4.4) 29(2.25,-4.4) 30(2.75,-4.4) 31(3.25,-4.4) 32(3.75,-4.4) 49(3.75,4.4) 50(3.25,4.4) 51(2.75,4.4) 52(2.25,4.4) 53(1.75,4.4) 54(1.25,4.4) 55(0.75,4.4) 56(0.25,4.4) 57(-0.25,4.4) 58(-0.75,4.4) 59(-1.25,4.4) 60(-1.75,4.4) 61(-2.25,4.4) 62(-2.75,4.4) 63(-3.25,4.4) 64(-3.75,4.4)
  rect 7.2x7.2 smd: 65(0,0)

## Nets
+5V: C46.1 C47.1 C48.1 C52.1 C63.1 C64.1 JP7.2 R98.2 R99.2 R105.2 R107.1 U8.1(IN#1) U8.2(IN#2) U8.4(BIAS) U9.5(1IN#5) U9.6(1IN#6) U9.11(2IN#11) U9.12(2IN#12)
VBUS: C16.1 D1.2(C) F1.2 L3.2 U4.65(VBUS)
VDD12: JP8.1 L6.1 L7.1 L8.1 L9.1 L10.1 R103.2
VDD12_LVDS: C81.1 C82.1 C83.1 C84.1 C85.1 L10.2 U1.20(VDD12_LVDS) U1.32(VDDP12_LVDS)
VDD12_PIN33: C59.1 C60.1 C61.1 C62.1 L6.2 R3.1
VDD18: JP5.3 JP9.1 JP12.1 R113.2
VDD33: C99.2 C100.2 J19.1(DVCC) J20.3 JP5.1 JP10.1 JP12.3 L5.1 R117.2 R119.2
VDD33_UC: C24.1 C26.2 C27.2 C28.1 C31.2 JP4.1 LED4.2(ANODE) R68.1 R72.2 R77.1 R78.2 R79.2 U4.11(AVCC1) U4.18(DVCC1) U4.50(DVCC2) U5.15(VCCB) U6.7(VCCB)
VDD33C: C54.1 C55.1 C56.1 C57.1 C58.1 L5.2 R5.1 R6.1 R7.1 R8.1 R9.1 R10.1 R11.1 R12.1 R13.1 R14.1 R15.1 R16.1 R17.1 R18.1 R19.1 R20.1 R40.1 R41.1 R42.1 R43.1 R44.1 R45.1 R46.1 R47.1 U1.31(VDD33_B) U1.56(VDD33_A)
VDD_12.0V_EXTERNAL: C37.1 J18.1 U7.3(VIN#3) U7.4(VIN#4)
VDD_I2C: C30.2 JP5.2 JP6.1 R81.1 R82.1 R83.2 U6.3(VDDA)
VDDIO: C25.2 C88.1 C89.1 C90.2 JP6.2 JP11.1 JP12.2 L11.1 R60.2 R61.2 R62.2 R76.2 R87.2 R91.2 U5.2(VCCA)
VDDIOC: C91.1 C92.1 C93.1 C94.1 L11.2 U1.3(VDDIO)
VDDL12C: C75.1 C76.1 C77.1 C78.1 C95.1 L9.2 U1.6(VDDL12_0) U1.44(VDDL12_1)
VDDP12_0: C67.1 C68.1 C69.1 C70.1 C86.1 L7.2 U1.51(VDDP12_CH0) U1.52(VDDR12_CH0)
VDDP12_1: C71.1 C72.1 C73.1 C74.1 C87.1 L8.2 U1.57(VDDR12_CH1) U1.60(VDDP12_CH1)
VSS: C1.1 C2.1 C5.1 C8.1 C10.1 C12.2 C13.2 C14.2 C15.2 C16.2 C17.1 C18.2 C19.2 C20.2 C21.2 C22.2 C23.1 C24.2 C25.1 C26.1 C27.1 C28.2 C29.2 C30.1 C31.1 C32.2 C33.2 C34.2 C35.2 C37.2 C38.2 C39.2 C40.2 C41.2 C43.2 C44.2 C46.2 C47.2 C48.2 C49.2 C50.2 C51.2 C52.2 C53.2 C54.2 C55.2 C56.2 C57.2 C58.2 C59.2 C60.2 C61.2 C62.2 C63.2 C64.2 C65.1 C66.2 C67.2 C68.2 C69.2 C70.2 C71.2 C72.2 C73.2 C74.2 C75.2 C76.2 C77.2 C78.2 C79.1 C80.2 C81.2 C82.2 C83.2 C84.2 C85.2 C86.2 C87.2 C88.2 C89.2 C90.1 C91.2 C92.2 C93.2 C94.2 C95.2 C99.1 C100.1 C101.2 C102.1 C103.1 C104.1 D1.1(A) J1.5 J1.6 J1.7 J1.8 J2.2 J2.3 J2.4 J2.5 J3.2 J3.3 J3.4 J3.5 J4.2 J4.3 J4.4 J4.5 J5.2 J5.3 J5.4 J5.5 J6.2 J6.3 J6.4 J6.5 J7.2 J7.3 J7.4 J7.5 J8.2 J8.3 J8.4 J8.5 J9.2 J9.3 J9.4 J9.5 J10.5 J10.8 J10.9 J11.9 J12.5 J13.4 J14.1 J14.3 J14.5 J14.7 J14.9 J14.11 J14.13 J15.1 J15.4 J15.5 J15.8 J15.9 J15.12 J15.13 J15.16 J15.17 J15.20 J16.1 J16.4 J16.5 J16.8 J16.9 J16.12 J16.13 J16.16 J16.17 J16.20 J17.1 J17.3 J17.5 J17.7 J17.9 J17.11 J17.13 J17.15 J17.17 J17.19 J18.2 J18.3 J19.20(DVSS) J20.10 J21.1 J21.3 JP1.2 JP2.2 JP3.1 JP4.2 JP8.2 JP9.2 JP10.2 JP11.2 LED1.1(CATHODE) LED2.1(CATHODE) LED3.1(CATHODE) Q1.2(SOURCE) R21.2 R22.2 R23.2 R24.2 R25.2 R26.2 R27.2 R28.2 R29.2 R30.2 R31.2 R32.2 R33.2 R34.2 R35.2 R36.2 R48.2 R49.2 R50.2 R52.2 R53.2 R54.2 R55.2 R56.2 R57.2 R58.2 R59.2 R65.2 R70.2 R71.2 R101.2 R106.1 R108.1 R109.2 R110.1 R115.1 R116.1 S3.4(B3) S3.5(B2) S3.6(B1) S5.1(A1) S5.3(A2) S5.5(A3) S5.7(A4) S5.9(A5) S5.11(A6) S5.13(A7) S5.15(A8) SW1.1 SW3.1 TP1.1 TP2.1 TP3.1 TP4.1 TP5.1 TP6.1 TP7.1 TP8.1 TP9.1 TP10.1 TP11.1 TP12.1 U1.65(DAP) U2.4(GND) U2.9(PWPD) U3.3(GND) U4.14(AVSS1) U4.19(DVSS1) U4.49(DVSS2) U4.61(VSSU) U4.68(AVSS2) U5.9(GND) U6.2(GND) U7.10(AGND) U7.13(PGND#13) U7.14(PGND#14) U7.21(DAP) U8.6(GND) U8.11(PWPD) U9.3(1GND) U9.9(2GND) U9.29(PWPD)
AIN_B_0: U4.1(P6.4/CB4/A4)
AIN_B_1: U4.2(P6.5/CB5/A5)
BISTC: J14.4 JP3.2 R61.1 S3.2(A2) U1.4(BISTC/INTB)
BISTEN: J14.2 R62.1 S3.1(A1) U1.5(BISTEN/TESTEN)
CAPI2S: C10.2 U1.2(CAP_I2S)
CLK1+: J15.15 R89.2 U1.36(CLK1+)
CLK1-: J15.14 R89.1 U1.37(CLK1-)
CLK2+: J16.15 R95.2 U1.23(CLK2+)
CLK2-: J16.14 R95.1 U1.24(CLK2-)
D0+: J15.3 R80.2 U1.42(D0+)
D0-: J15.2 R80.1 U1.43(D0-)
D1+: J15.7 R86.2 U1.40(D1+)
D1-: J15.6 R86.1 U1.41(D1-)
D2+: J15.11 R88.2 U1.38(D2+)
D2-: J15.10 R88.1 U1.39(D2-)
D3+: J15.19 R90.2 U1.34(D3+)
D3-: J15.18 R90.1 U1.35(D3-)
D4+: J16.3 R92.2 U1.29(D4+)
D4-: J16.2 R92.1 U1.30(D4-)
D5+: J16.7 R93.2 U1.27(D5+)
D5-: J16.6 R93.1 U1.28(D5-)
D6+: J16.11 R94.2 U1.25(D6+)
D6-: J16.10 R94.1 U1.26(D6-)
D7+: J16.19 R96.2 U1.21(D7+)
D7-: J16.18 R96.1 U1.22(D7-)
D_GPIO0: J14.14 U1.19(D_GPIO0/MOSI)
D_GPIO1: J14.12 U1.18(D_GPIO1/MISO)
D_GPIO2: J14.10 U1.17(D_GPIO2/SPLK)
D_GPIO3: J14.8 U1.16(D_GPIO3/SS)
DM: R66.2 U4.64(PU.1/DM)
DOUT+: C9.2 U1.62(CMLOUTP)
DOUT-: C11.2 U1.63(CMLOUTM)
DP: R67.2 R69.1 U4.62(PU.0/DP)
GPIO0: J17.2 JP2.1 R2.2 U1.7(SDOUT/GPIO0/PASS)
GPIO0/I2C(SDA): J12.1 U4.46(P4.1/PM_UCB1SIMO/PM_UCB1SDA) U6.1(SDA_B)
GPIO1: J17.4 U1.8(SWC/GPIO1)
GPIO1/I2C(SCL): J12.2 U4.47(P4.2/PM_UCB1SOMI/PM_UCB1SCL) U6.8(SCL_B)
GPIO2/SPI(SCLK): J12.3 U4.45(P4.0/PM_UCB1STE/PM_UCA1CLK) U5.12(B4)
GPIO3/PWM2: J12.4 R73.1 U4.33(P2.4/TA2.1)
GPIO4/SPI(SIMO)/UART(TXD): J12.7 U4.52(P4.5/PM_UCA1RXD/PM_UCA1SOMI) U5.11(B5)
GPIO5/SPI(SOMI)/UART(RXD): J12.8 U4.51(P4.4/PM_UCA1TXD/PM_UCA1SIMO) U5.10(B6)
GPIO6/PWM1/SPI(CS): J12.9 U4.29(P2.0/TA1.1) U5.13(B3)
GPIO7/PWM0: J12.10 R74.1 U4.23(P1.2/TA0.1)
GPIO8/ADC3: U4.4(P6.7/CB7/A7)
GPIO9/ADC2: U4.3(P6.6/CB6/A6)
GPIO10/VEREF-: U4.10(P5.1/A9/VREF-/VEREF-)
GPIO11/VEREF+: C23.2 U4.9(P5.0/A8/VREF+/VEREF+)
I2C_SCL: J19.14(SCL) R82.2 R85.1 U1.45(I2C_SCL) U6.5(SCL_A)
I2C_SDA: J19.15(SDA) R81.2 R84.1 U1.46(I2C_SDA) U6.4(SDA_A)
I2S_CLK: J17.18 U1.13(I2S_CLK/GPIO8_REG)
I2S_DA: J17.14 U1.12(I2S_DA/GPIO6_REG)
I2S_DB: J17.12 U1.11(I2S_DB/GPIO5_REG)
I2S_DC: J17.6 U1.10(I2S_DC/GPIO2)
I2S_DD: J17.8 U1.9(I2S_DD/GPIO3)
I2S_WC: J17.16 U1.14(I2S_WC/GPIO7_REG)
IDX: C104.2 S4.2(B1) S4.4(B2) S4.6(B3) S4.8(B4) S4.10(B5) S4.12(B6) S4.14(B7) S4.16(B8) U1.47(IDX)
INTB: J19.9(P2.1) U5.3(A2)
INTB_CTRL: R74.2 U5.14(B2)
LOCK: JP1.1 R1.2 U1.1(LOCK)
MCLK: J17.20 U1.15(MCLK)
MISO: J19.3(P1.1) U5.6(A5)
MODE_SEL0: C102.2 S1.2(B1) S1.4(B2) S1.6(B3) S1.8(B4) S1.10(B5) S1.12(B6) S1.14(B7) S1.16(B8) U1.61(MODE_SEL0)
MODE_SEL1: C103.2 S2.2(B1) S2.4(B2) S2.6(B3) S2.8(B4) S2.10(B5) S2.12(B6) S2.14(B7) S2.16(B8) U1.50(MODE_SEL1)
MOSI: J19.4(P1.2) U5.7(A6)
PDB: C12.1 J19.13(P2.5) R60.1 R120.1 S3.3(A3) SW1.2 U1.48(PDB)
PDB_CTRL: R73.2 U5.16(B1)
PUR: R69.2 R71.1 SW2.1 U4.63(PUR)
RINA+: C3.1 J1.2 L1.3 L1.4 R37.2
RINA-: C4.1 J1.4 L1.1 L1.2 R38.2
RINB+: C6.1 J1.1 L2.3 L2.4 R63.2
RINB-: C7.1 J1.3 L2.1 L2.2 R64.2
RST: C101.1 J19.16(RST) J20.2 J21.2 R119.1 SW3.2
SCLBRD: R79.1 U4.38(P3.1/UCB0SOMI/UCB0SCL)
SDABRD: R78.1 U4.37(P3.0/UCB0SIMO/UCB0SDA)
SPLK: J19.6(P1.4) U5.5(A4)
SS: J19.5(P1.3) U5.4(A3)
SW0: J19.2(P1.0) S5.2(B1)
SW1: J19.7(P1.5) S5.4(B2)
SW2: J19.8(P2.0) S5.6(B3)
SW3: J19.10(P2.2) S5.8(B4)
SW4: J19.19(P2.6) S5.10(B5)
SW5: J19.18(P2.7) S5.12(B6)
SW6: J19.12(P2.4) S5.14(B7)
SW7: J19.11(P2.3) S5.16(B8)
TCK: J11.7 U4.75(PJ.3/TCK)
TDI: J11.3 U4.73(PJ.1/TDI/TCLK)
TDO: J11.1 U4.72(PJ.0/TDO)
TEST: J19.17(TEST) J20.7 J21.4 R118.2
TEST1: J11.8 U4.71(TEST/SBWTCK)
TMS: J11.5 U4.74(PJ.2/TMS)
VUSB: C18.1 SW2.2 U4.66(VUSB)
~RST: C22.1 J11.11 R72.1 U4.76(~RST/NMI/SBWTDIO)
N15364431: C38.1 C39.1 C40.1 C41.1 JP7.1 L4.2 R99.1 R102.1 U7.12(OUT)
N15364577: C36.2 D3.1(CATHODE) L4.1 R97.1 U7.17(SW#17) U7.18(SW#18)
N15364585: R97.2 U7.19(PRE)
N15364743: C35.1 U7.1(VCC)
N15364759: C44.1 U7.11(SS)
N15364779: C43.1 U7.9(RAMP)
N15364847: R101.1 U7.8(RT)
N15364875: C42.1 R100.1 R102.2 R106.2 U7.7(FB)
N15364879: C42.2 C45.2 U7.6(COMP)
N15364919: C45.1 R100.2
N15365001: D3.2(ANODE) U7.15(IS_2) U7.16(IS_1)
N15365029: C36.1 U7.20(BST)
N16848563: C29.1 U4.20(VCORE)
N16848714: C21.1 U4.67(V18)
N16849932: J10.3 R67.1 U3.4(IO3)
N16849951: C17.2 F1.1 J10.1 U3.6(VCC)
N16849953: J10.2 R66.1 U3.1(IO1)
N16849991: J10.6 J10.7 R70.1
N16930628: Q1.1(GATE) U4.15(P8.0)
N17059131: J20.8 R118.1
N17075556: C6.2 U1.58(RIN+)
N17075562: C7.2 U1.59(RIN-)
N17075662: C5.2 U1.55(CMF)
N17075712: C3.2 U1.53(RIN0+)
N17075718: C4.2 U1.54(RIN0-)
N17084124: J17.10 R91.1
N17084564: C34.1 J13.2 R85.2
N17084583: C33.1 J13.3 R84.2
N17084590: C32.1 J13.1($PIN0) R83.1
N17084985: J4.1 R38.1 R50.1
N17084987: J2.1 J3.1 R37.1
N17087573: J9.1 R64.1 R65.1
N17087575: J7.1 J8.1 R63.1
N17097514: R43.2 R55.1 S4.9(A5)
N17097522: R42.2 R54.1 S4.11(A6)
N17097524: R41.2 R53.1 S4.13(A7)
N17097526: R47.2 R59.1 S4.1(A1)
N17097528: R45.2 R57.1 S4.5(A3)
N17097530: R46.2 R58.1 S4.3(A2)
N17097532: R44.2 R56.1 S4.7(A4)
N17097556: R40.2 R52.1 S4.15(A8)
N17103018: C11.1 J6.1 R49.1
N17103031: C9.1 J5.1 R48.1
N17121993: R77.2 U6.6(OE)
N17123672: C19.1 U4.70(P5.3/XT2OUT) Y1.2
N17123682: C20.1 U4.69(P5.2/XT2IN) Y1.1
N17132631: C14.1 L3.1 U2.5(EN) U2.8(IN)
N17133396: C15.1 U2.3(NR/FB)
N17133657: C13.1 R68.2 U2.1(OUT)
N17138963: C2.2 U1.49(CAP_PLL0)
N17143987: C8.2 U1.64(CAP_PLL1)
N17154309: LED2.2(ANODE) R2.1
N17160541: R76.1 U5.8(OE)
N17174458: R3.2 R4.1 U1.33(VDD25_CAP)
N17176193: C1.2 R4.2
N17179271: C49.1 C50.1 R103.1 R104.2 U8.9(OUT#9) U8.10(OUT#10)
N17179285: R104.1 R108.2 U8.8(FB)
N17180621: C51.1 U8.7(SS)
N17181839: R105.1 U8.3(PG)
N17182034: C53.1 R107.2 R109.1 U8.5(EN)
N17191311: LED3.2(ANODE) R98.1
N17214938: C79.2 C80.1 R114.1 R117.1 U9.17(2OUT#17) U9.18(2OUT#18)
N17214967: C65.2 C66.1 R111.1 R112.1 R113.1 U9.23(1OUT#23) U9.24(1OUT#24)
N17217834: R114.2 U9.22(2\R\E\S\E\T\)
N17220662: R111.2 U9.28(1\R\E\S\E\T\)
N17221888: R110.2 R112.2 U9.25(1FB/NC)
N17228595: R116.2 U9.10(2\E\N\)
N17228599: R115.2 U9.4(1\E\N\)
N17278417: R10.2 R26.1 S1.5(A3)
N17278419: R8.2 R24.1 S1.9(A5)
N17278425: R11.2 R27.1 S1.3(A2)
N17278439: R9.2 R25.1 S1.7(A4)
N17278441: R6.2 R22.1 S1.13(A7)
N17278443: R7.2 R23.1 S1.11(A6)
N17278445: R5.2 R21.1 S1.15(A8)
N17278449: R12.2 R28.1 S1.1(A1)
N17278561: R16.2 R32.1 S2.9(A5)
N17278569: R15.2 R31.1 S2.11(A6)
N17278593: R14.2 R30.1 S2.13(A7)
N17278595: R20.2 R36.1 S2.1(A1)
N17278597: R18.2 R34.1 S2.5(A3)
N17278599: R19.2 R35.1 S2.3(A2)
N17278601: R17.2 R33.1 S2.7(A4)
N17278603: R13.2 R29.1 S2.15(A8)
N17395731: LED1.2(ANODE) R1.1
N17653350: R120.2 U5.1(A1)
N171178020: Q1.3(DRAIN) R75.2
N173796350: LED4.1(CATHODE) R75.1
N175788770: J14.6 R87.1

Pads without a net: J10 4; J11 2 4 6 10 12 13 14; J12 6; J20 1 4 5 6 9 11 12 13 14; U2 2 6 7; U3 2 5; U4 5 6 7 8 12 13 16 17 21 22 24 25 26 27 28 30 31 32 34 35 36 39 40 41 42 43 44 48 53 54 55 56 57 58 59 60 77 78 79 80; U7 2 5; U9 1 2 7 8 13 14 15 16 19 20 21 26 27

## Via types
v1: diameter 0.508, hole 0.254, TOP to BOTTOM, 1543 vias
v2: diameter 0.66, hole 0.33, TOP to BOTTOM, 25 vias

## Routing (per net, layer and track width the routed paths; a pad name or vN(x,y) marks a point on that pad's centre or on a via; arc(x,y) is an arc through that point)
+5V: length 3.9
  TOP w0.254: U8.4 73.46,170.82 72.6,169.95 v1(70.81,169.95)
  vias: v1(60.83,154.94) v1(60.83,153.67) v1(60.83,152.4) v1(60.83,150.88) v1(60.83,149.61) v1(60.83,148.34) v1(62.74,154.94) v1(62.74,153.67) v1(62.74,152.4) v1(62.74,150.88) v1(62.74,149.61) v1(62.74,148.34) v1(65.41,173.36) v1(65.41,172.09) v1(65.41,170.81) v1(65.41,169.55) v1(65.41,168.28) v1(65.66,153.21) v1(65.71,148.72) v1(65.96,149.25) v1(66.12,152.81) v1(67.31,173.36) v1(67.31,172.09) v1(67.31,170.81) v1(67.31,169.55) v1(67.31,168.28) v1(68.45,171.73) v1(68.45,170.46) v1(69.47,171.73) v1(69.47,170.46) v1(69.82,168.96)
VBUS: length 29.5
  TOP w0.305: v1(34.77,127.99) 34.77,128.02 35.45,127.34 U4.65
  BOTTOM w0.889: v1(34.77,127.99) 34.32,128.45 31.14,128.45 22.38,137.21 22.38,148.46
  vias: v1(11.86,150.29) v1(12.77,150.28) v1(13.63,150.29) v1(13.95,148.99) v1(24.05,150.77) v1(24.08,149.99) v1(24.05,149.17)
VDD12:
  vias: v1(20.59,85.94) v1(20.7,86.87) v1(21.52,86.87) v1(23.97,68.11) v1(24.89,67.18) v1(25.82,68.11) v1(35.34,67.58) v1(35.3,66.55) v1(35.4,65.49) v1(36.47,66.45) v1(36.47,65.38) v1(40.8,69.48) v1(40.8,68.59) v1(42.07,68.34) v1(53.54,92.81) v1(54.36,93.55) v1(55.17,92.79) v1(80.98,175.62) v1(80.98,174.73) v1(82.88,175.62) v1(82.88,174.73) v1(84.79,175.62) v1(85.42,174.73) v1(85.42,173.46) v1(86.69,175.62) v1(86.69,174.73) v1(86.69,173.46) v1(88.21,175.62) v1(88.21,174.73) v1(88.21,173.46)
VDD12_LVDS: length 4.7
  TOP w0.178: v1(43.92,79.29) U1.20
  TOP w0.254: U1.32 43.62,85.29 43.84,85.51 43.84,85.85
  TOP w0.381: 43.84,85.85 v1(43.84,86.16)
  TOP w0.508: v1(44.6,86.16) v1(43.84,86.16)
VDD12_PIN33: length 2.3
  TOP w0.508: R3.1 43.49,88.94 v1(43.76,89.21) 43.85,89.29 v1(45.05,89.29)
  vias: v1(50.88,91.08) v1(50.88,90.42) v1(53.24,90.47) v1(53.29,91.16)
VDD18:
  vias: v1(83.31,158.12) v1(83.31,156.84) v1(83.31,155.57) v1(83.31,154.31) v1(85.22,158.12) v1(85.22,156.84) v1(85.22,155.57) v1(85.22,154.31) v1(87.12,158.12) v1(87.12,156.84) v1(87.12,155.57) v1(87.12,154.31)
VDD33: length 4.7
  TOP w0.508: R119.2 v1(94.87,164.87)
  BOTTOM w0.508: J20.3 92.58,145.67 C100.2 ; C99.2 J19.1
  vias: v1(58.9,93.55) v1(59.72,92.96) v1(59.72,92.41) v1(82.17,147.83) v1(82.17,146.56) v1(83.52,149.07) v1(83.52,147.8) v1(83.52,146.53) v1(85.42,149.07) v1(87.33,149.07) v1(87.33,147.8) v1(87.33,146.53)
VDD33_UC: length 12
  TOP w0.254: U5.15 v1(53.54,138.46) ; U6.7 69.73,140.82 69.7,140.85 v1(69.7,140.89)
  TOP w0.305: U4.11 v1(43.43,116.71) ; U4.18 v1(46.93,116.71)
  TOP w0.33: LED4.2 v1(55.63,113.04) ; U4.50 v1(43.43,132.46)
  TOP w0.508: v1(69.7,140.89) 69.25,141.34 R77.1 ; C26.2 53.39,138.3 v1(53.54,138.46) ; v1(43.43,116.71) 43.37,116.66 C28.1
  BOTTOM w0.508: v1(69.7,140.89) 69.7,140.87 69.6,140.77 C31.2 ; v1(43.43,132.46) 43.43,132.45 C24.1
  vias: v1(38.96,150.06) v1(38.96,148.79) v1(40.49,150.06) v1(40.49,148.79) v1(40.49,147.52) v1(42.01,150.06) v1(42.01,148.79) v1(42.01,147.52) v1(43.54,150.06) v1(43.54,148.79) v1(54.1,128.27) v1(54.81,128.32) v1(54.89,129.18) v1(54.99,127.41)
VDD33C: length 39.5
  TOP w0.178: U1.56 31.33,81.79 v1(31.33,81.78)
  TOP w0.254: v1(44.02,84.87) 43.87,84.87 43.79,84.79 U1.31
  TOP w0.508: v1(44.02,84.87) 44.33,84.87 v1(44.53,85.07)
  BOTTOM w0.178: v1(31.33,81.78) 32.68,81.78 C57.1
  BOTTOM w0.508: R46.1 v1(49.66,19.18) ; R19.1 v1(26.29,10.36) ; R8.1 v1(59,10.36) ; R40.1 v1(66.55,19.18) ; R47.1 v1(46.86,19.18) ; R41.1 v1(63.75,19.18) ; R18.1 v1(29.08,10.36) ; R6.1 v1(64.59,10.36) ; R17.1 v1(31.88,10.36) ; R7.1 v1(61.8,10.36) ; R44.1 v1(55.24,19.18) ; R14.1 v1(40.26,10.36) ; R5.1 v1(67.39,10.36) ; R20.1 v1(23.49,10.36) ; R15.1 v1(37.46,10.36) ; R43.1 v1(58.04,19.18) ; R13.1 v1(43.05,10.36) ; R42.1 v1(60.96,19.18) ; R10.1 v1(53.42,10.36) ; R45.1 v1(52.45,19.18) ; R12.1 v1(47.83,10.36) ; R11.1 v1(50.62,10.36) ; R16.1 v1(34.67,10.36) ; R9.1 v1(56.21,10.36)
  vias: v1(56.21,89.94) v1(56.97,89.89) v1(58.01,91.11) v1(57.99,90.2) v1(87.88,18.26) v1(87.88,16.99) v1(87.88,15.72) v1(89.79,18.26) v1(89.79,16.99) v1(89.79,15.72) v1(91.69,18.26) v1(91.69,16.99) v1(91.69,15.72)
VDD_12.0V_EXTERNAL:
  vias: v1(10.87,166.88) v1(10.87,164.97) v1(10.87,163.07) v1(13.41,166.88) v1(13.41,164.97) v1(13.41,163.07) v1(15.95,166.88) v1(15.95,164.97) v1(15.95,163.07) v1(15.95,162.05) v1(18.49,163.07) v1(18.49,162.05) v1(23.57,161.8) v1(23.83,161.29)
VDD_I2C: length 5.6
  TOP w0.254: v1(70.48,135.89) 70.23,136.15 U6.3
  BOTTOM w0.381: C30.2 70.23,137.16 70.23,136.15 v1(70.48,135.89)
  BOTTOM w0.635: R82.1 v1(89.24,122.26) ; R83.2 v1(92.19,124.62) ; R81.1 v1(89.24,116.75)
VDDIO: length 156.4
  TOP w0.33: U5.2 v1(61.72,138.46) 61.87,138.3 C25.2
  TOP w0.508: R60.2 v1(75.95,29.49) ; R61.2 v1(78.49,29.36) ; R62.2 v1(81.03,29.36)
  TOP w0.635: R76.2 v1(61.76,144.11)
  BOTTOM w0.635: R87.2 67.06,49.43 ; R91.2 36.58,49.4
  BOTTOM w1.27: 87.07,50.11 87.07,35.4 v1(81.03,29.36) v1(78.49,29.36) 76.07,29.36 v1(75.95,29.49) ; 87.07,50.11 JP6.2 83.34,114.37 JP12.2 ; 87.07,50.11 67.74,50.11 67.06,49.43 67.08,49.4 36.58,49.4 36.58,49.4
  vias: v1(31.47,111.12) v1(31.47,110.06) v1(32.74,111.12) v1(32.74,110.06)
VDDIOC: length 2.5
  TOP w0.254: U1.3 35.15,75.45 v1(35.15,75.45) 34.63,74.93 v1(34.52,74.93)
  vias: v1(80.11,110.54) v1(80.06,109.42) v1(80.87,110.49) v1(80.95,109.45)
VDDL12C: length 5.4
  TOP w0.178: v1(36.15,87.63) U1.44 ; U1.6 36.65,75.45 36.68,75.43 36.68,75.34 v1(36.65,75.31)
  TOP w0.254: v1(35.56,88.32) v1(36.14,88.32) 36.15,88.31 v1(36.15,87.63) ; v1(36.65,75.31) v1(36.65,74.73)
VDDP12_0: length 4.1
  TOP w0.178: 31.94,84.06 32.21,83.79 U1.52 ; 31.94,84.06 32.17,84.29 U1.51 ; 31.94,84.06 v1(31.92,84.06)
  TOP w0.254: v1(31.39,84.61) 31.39,84.58 v1(31.92,84.06)
VDDP12_1: length 3.2
  TOP w0.178: U1.57 31.93,81.29 v1(31.92,81.28) ; v1(31.92,79.8) 31.93,79.79 U1.60
  vias: v1(24.46,70.69) v1(25.17,70.69) v1(25.81,71.91) v1(25.78,70.69) v1(25.78,69.8) v1(32.61,77.23)
VSS: length 94.7
  TOP w0.178: v1(69.47,136.04) 69.73,136.3 U6.2 ; v1(47.24,119.13) 47.43,118.94 U4.19
  TOP w0.229: v1(78.03,170.08) 77.78,170.32 U8.6
  TOP w0.254: U9.9 66.18,150.66 v1(66.04,150.8) ; U4.61 35.66,129.34 v1(35.18,129.82) ; v1(66.01,154.99) 66.44,154.56 U9.3 ; U3.3 v1(11.43,142.37)
  TOP w0.305: U2.4 v1(34.24,148.94) ; v1(53.21,142.36) 53.22,142.36 U5.9 ; U4.68 37.75,125.84 v1(38.4,126.49) ; U4.14 v1(44.93,116.71) ; v1(44.21,132.53) 44.21,132.48 43.93,132.2 U4.49
  TOP w0.381: v1(10.11,140.89) J10.5 ; R49.2 v1(25.67,73.55) ; C17.1 v1(14,147.19) ; R48.2 v1(25.67,79.42) ; U7.10 v1(26.9,157.09) ; C15.2 v1(35.56,149.78)
  TOP w0.432: U7.14 v1(32.52,159.04) ; U7.13 v1(32.52,158.39)
  TOP w0.508: TP9.1 49.89,75.53 49.9,75.53 v1(50.03,75.53) ; TP2.1 30.42,94.63 30.43,94.64 v1(30.43,94.77) ; v1(6.3,149.61) R70.2 v1(7.12,150.41) ; LED2.1 v1(20.43,14.49) ; TP4.1 41.03,94.63 41.03,94.64 v1(41.03,94.77) ; v1(44.57,94.77) 44.57,94.64 44.56,94.63 TP6.1 ; TP10.1 49.89,86.14 49.9,86.13 v1(50.03,86.13) ; TP1.1 33.96,94.63 33.96,94.64 v1(33.96,94.77) ; v1(50.03,79.06) 49.9,79.06 49.89,79.07 TP7.1 ; TP3.1 37.49,94.63 37.5,94.64 v1(37.5,94.77) ; C18.2 v1(14.85,136.53) ; C101.2 v1(95,157.91) ; v1(50.03,71.99) 49.9,71.99 49.89,72 TP11.1 ; C25.1 v1(62.74,136.57) ; C26.1 v1(52.83,136.7) ; TP12.1 49.89,89.67 49.9,89.67 v1(50.03,89.67) ; TP8.1 49.89,82.6 49.9,82.6 v1(50.03,82.6) ; R71.2 v1(16.27,136.53) ; LED1.1 v1(21.34,22.23)
  TOP w0.635: JP1.2 20.31,20.05 LED1.1 ; v1(95.28,21.61) SW1.1 v1(93.38,20.04) ; S5.1 v1(59.94,108.59) ; v1(35.83,153.67) R106.1 v1(34.63,152.47) ; S5.11 v1(72.64,108.59) ; C19.2 v1(33.14,123.2) ; S5.5 v1(65.02,108.59) ; S5.3 v1(62.48,108.59) ; JP2.2 20.43,11.61 LED2.1 ; S5.7 v1(67.56,108.59) ; S5.13 v1(75.18,108.59) ; v1(49.57,111.37) Q1.2 48.38,112.46 v1(48.37,112.45) ; v1(93.95,24.89) C12.2 v1(92.33,26.6) ; C20.2 v1(33.14,126.99) ; v1(45.27,113.68) C28.2 v1(46.56,114.81) ; S5.15 v1(77.72,108.59) ; S5.9 v1(70.1,108.59)
  BOTTOM w0.381: C90.1 v1(78.23,114.17) ; C24.2 v1(43.43,130.1) ; C30.1 v1(69.09,137.9)
  BOTTOM w0.508: R65.2 v1(2.54,51.64) ; C32.2 v1(95.12,125.55) ; C62.2 45.02,91.71 v1(44.66,92.07) ; R50.2 v1(2.54,99.26) ; C99.1 v1(58.29,125.83) ; 90.81,146.69 v1(90.02,146.69) ; C61.2 43.87,91.87 v1(43.8,91.94) ; C22.2 v1(38.4,121.79) ; C1.1 v1(46.53,88.39) ; C102.1 v1(70.74,6.98) ; C103.1 v1(21.34,6.98) ; C21.2 v1(38.4,126.49) ; C23.1 v1(42.42,119.1) ; C104.1 v1(70.1,21.87) ; C31.1 v1(71.35,139.83)
  BOTTOM w0.635: C33.2 v1(94.2,117.33) ; R116.1 68.24,149.61 v1(68.8,149.04) ; C34.2 v1(94.2,122.06) ; R110.1 76.85,155.7 v1(76.35,156.2)
  vias: v1(0.63,117.27) v1(0.63,108.76) v1(0.63,101.4) v1(0.63,92.89) v1(0.63,69.65) v1(0.63,61.14) v1(0.63,53.77) v1(0.63,45.26) v1(0.63,37.9) v1(0.63,29.39) v1(0.63,22.02) v1(0.63,13.51) v1(1.23,80.22) v1(1.25,81.8) v1(1.77,78.98) v1(2.06,83.27) v1(2.26,136.65) v1(2.54,163.83) v1(2.54,160.02) v1(2.54,154.94) v1(2.54,151.13) v1(2.5,121.72) v1(2.54,117.27) v1(2.54,108.76) v1(2.54,101.4) v1(2.54,92.89) v1(2.54,69.65) v1(2.54,61.14) v1(2.54,53.77) v1(2.54,45.26) v1(2.54,37.9) v1(2.54,29.39) v1(2.54,22.02) v1(2.54,13.51) v1(3.15,136.65) v1(3.33,80.5) v1(3.36,81.59) v1(3.68,125.81) v1(4.01,136.58) v1(4.15,82.41) v1(4.44,117.27) v1(4.44,108.76) v1(4.44,101.4) v1(4.44,92.89) v1(4.44,69.65) v1(4.44,61.14) v1(4.44,53.77) v1(4.44,45.26) v1(4.44,37.9) v1(4.44,29.39) v1(4.44,22.02) v1(4.44,13.51) v1(4.53,121.72) v1(5.08,160.02) v1(5.08,129.54) v1(5.33,112.22) v1(5.28,97.97) v1(5.32,83.58) v1(5.55,96.34) v1(5.45,16.88) v1(5.65,50.33) v1(5.55,18.81) v1(5.92,32.68) v1(6.35,163.83) v1(6.35,154.94) v1(6.35,151.13) v1(6.35,64.5) v1(6.35,48.63) v1(6.42,113.82) v1(6.37,87.61) v1(6.65,34.3) v1(6.84,19.65) v1(6.9,112.18) v1(6.91,30.58) v1(6.91,28.68) v1(6.89,26.77) v1(6.91,24.34) v1(6.91,22.43) v1(7.01,97.97) v1(7.27,17.44) v1(7.37,66.28) v1(7.37,50.41) v1(7.45,96.34) v1(7.58,136.55) v1(7.99,89.21) v1(8.13,33.11) v1(8.2,86.45) v1(8.33,113.82) v1(8.25,64.5) v1(8.25,48.63) v1(8.47,136.55) v1(8.47,18.93) v1(8.61,31.67) v1(8.56,26.75) v1(8.74,30.2) v1(8.69,28.5) v1(8.69,23.93) v1(8.69,22.02) v1(8.69,20.12) v1(8.81,112.15) v1(9.34,136.47) v1(9.28,66.28) v1(9.28,50.41) v1(9.36,96.34) v1(9.45,90.71) v1(9.55,97.97) v1(9.6,87.84) v1(9.68,24.79) v1(10.03,125.81) v1(9.96,82) v1(10.23,113.79) v1(10.16,64.59) v1(10.16,48.72) v1(10.16,26.72) v1(10.4,79.41) v1(10.81,145.36) v1(10.95,111.68) v1(10.95,98.48) v1(11.01,92.25) v1(10.96,66.05) v1(11.06,89.33) v1(11.23,96.68) v1(11.23,62.36) v1(11.23,60.46) v1(11.23,56.02) v1(11.23,54.12) v1(11.16,51.4) v1(11.3,58.12) v1(11.35,109.7) v1(11.35,107.72) v1(11.35,105.82) v1(11.35,103.28) v1(11.35,100.74) v1(11.39,81.59) v1(11.63,124.71) v1(11.59,49.19) v1(11.63,24.89) v1(11.84,26.97) v1(11.95,112.97) v1(12,79.49) v1(12.48,94.19) v1(12.45,64.86) v1(12.46,49.84) v1(12.59,98.02) v1(12.62,90.87) v1(12.7,173.99) v1(12.7,171.45) v1(12.7,129.54) v1(12.83,84.08) v1(12.89,111.32) v1(12.9,62.43) v1(12.9,60.53) v1(12.93,58.55) v1(12.93,52.55) v1(12.94,50.65) v1(12.96,109.41) v1(12.96,107.51) v1(12.96,103.7) v1(12.96,101.79) v1(12.96,99.89) v1(12.95,56.08) v1(12.95,54.18) v1(13.03,27.91) v1(13.08,95.91) v1(13.29,106.2) v1(13.27,79.49) v1(13.38,77.23) v1(13.35,76.15) v1(13.38,75.21) v1(13.41,74.06) v1(13.48,102.74) v1(13.48,100.84) v1(13.48,98.93) v1(13.48,97.77) v1(13.52,78.31) v1(13.53,72.55) v1(13.53,70.64) v1(13.52,68.31) v1(13.52,66.22) v1(13.52,64.14) v1(13.54,29.01) v1(13.56,59.21) v1(13.59,56.44) v1(13.6,54.87) v1(13.61,53.31) v1(13.6,51.55) v1(13.59,49.99) v1(13.59,47.91) v1(13.59,46) v1(13.59,44.1) v1(13.59,42.19) v1(13.59,40.29) v1(13.59,38.38) v1(13.59,36.48) v1(13.59,34.57) v1(13.59,32.67) v1(13.59,30.78) v1(13.9,92.5) v1(13.97,154.94) v1(13.97,153.67) v1(14.05,26.14) v1(14.1,84.08) v1(14.17,81.99) v1(14.76,94.22) v1(15.03,105.42) v1(15.14,27.69) v1(15.24,146.05) v1(15.48,95.92) v1(15.5,79.49) v1(15.54,58.24) v1(15.52,56.37) v1(15.52,54.47) v1(15.52,52.56) v1(15.52,50.66) v1(15.52,48.93) v1(15.52,46.85) v1(15.52,44.94) v1(15.52,43.04) v1(15.52,41.13) v1(15.52,39.23) v1(15.52,37.32) v1(15.52,35.42) v1(15.52,33.51) v1(15.52,31.61) v1(15.52,29.7) v1(15.63,78.14) v1(15.63,76.24) v1(15.63,74.33) v1(15.63,72.43) v1(15.63,71.59) v1(15.63,66.32) v1(15.63,64.24) v1(15.65,62.09) v1(15.61,60.25) v1(15.74,103.65) v1(15.74,101.58) v1(15.74,99.68) v1(15.74,97.77) v1(15.84,84.09) v1(15.9,68.3) v1(15.95,81.99) v1(16.51,173.99) v1(16.51,171.45) v1(16.51,156.21) v1(16.51,153.67) v1(16.51,125.73) v1(16.51,93.98) v1(16.52,69.59) v1(17.23,73.21) v1(17.23,70.44) v1(17.39,65.8) v1(17.66,142.17) v1(17.78,107.95) v1(17.78,104.14) v1(17.78,100.33) v1(19.05,146.05) v1(19.05,140.97) v1(19.05,137.16) v1(19.53,84.48) v1(20.07,153.92) v1(20.24,169.55) v1(20.24,168.28) v1(20.32,173.99) v1(20.32,171.45) v1(20.32,138.43) v1(20.32,135.89) v1(20.43,79.2) v1(20.43,76.15) v1(20.4,73.64) v1(20.39,68.94) v1(20.7,166.5) v1(20.95,153.92) v1(21.3,61.88) v1(21.33,54.14) v1(21.55,76.84) v1(21.52,74.55) v1(21.59,107.95) v1(21.59,104.14) v1(21.59,100.33) v1(21.59,96.52) v1(21.72,166.5) v1(21.7,84.08) v1(21.72,81.62) v1(21.73,72.28) v1(21.73,71.39) v1(21.77,169.55) v1(21.77,168.28) v1(22.4,153.39) v1(22.73,166.5) v1(23.04,79.48) v1(23.12,77.27) v1(23.12,75.27) v1(23.05,52.23) v1(23.29,169.55) v1(23.29,168.28) v1(23.26,81.98) v1(23.46,84.09) v1(23.76,49.29) v1(23.93,153.39) v1(23.92,51.44) v1(24.13,173.99) v1(24.13,171.45) v1(24.13,142.24) v1(24.13,100.33) v1(24.26,81.62) v1(24.39,79.51) v1(24.75,75.49) v1(24.82,169.55) v1(24.82,168.28) v1(24.82,167) v1(24.82,165.74) v1(24.87,77.45) v1(25.04,88.77) v1(25.2,153.39) v1(25.17,81.98) v1(25.4,107.95) v1(25.4,104.14) v1(25.4,99.06) v1(25.4,96.52) v1(25.37,84.09) v1(25.76,88.72) v1(25.96,57.3) v1(26.17,81.62) v1(26.34,169.55) v1(26.34,168.28) v1(26.34,167) v1(26.34,165.74) v1(26.29,73.17) v1(26.33,55.33) v1(26.47,153.39) v1(26.47,77.73) v1(26.47,75.24) v1(26.67,139.7) v1(26.67,135.89) v1(26.66,87.56) v1(26.8,164.21) v1(26.92,155.7) v1(26.92,154.81) v1(27.05,161.8) v1(27.05,158.24) v1(27.07,81.98) v1(27.27,84.09) v1(27.49,88.57) v1(27.54,77.78) v1(27.56,79.51) v1(27.86,169.55) v1(27.86,168.28) v1(27.86,167) v1(27.86,165.74) v1(27.92,75.18) v1(27.99,154.66) v1(27.99,153.39) v1(28.11,145.7) v1(28.1,144.66) v1(28.07,81.62) v1(28.19,160.02) v1(28.2,143.52) v1(28.23,88.75) v1(28.84,84.09) v1(28.98,81.98) v1(29.21,173.99) v1(29.21,171.45) v1(29.21,142.24) v1(29.21,139.7) v1(29.21,135.89) v1(29.34,161.8) v1(29.34,158.24) v1(29.39,169.55) v1(29.39,168.28) v1(29.39,167) v1(29.39,165.74) v1(29.46,155.83) v1(29.51,154.66) v1(29.51,153.39) v1(29.65,79.2) v1(29.57,53.7) v1(30.03,75.9) v1(30.12,86.84) v1(30.23,81.79) v1(30.48,99.06) v1(30.52,84.34) v1(30.99,76.74) v1(31.14,95.28) v1(31.21,97.12) v1(31.25,75.49) v1(31.43,52.16) v1(31.75,101.6) v1(32.21,148.05) v1(32.22,146.83) v1(32.31,149.83) v1(32.27,107.84) v1(32.31,107.08) v1(32.34,106.16) v1(32.45,98.44) v1(32.71,147.45) v1(33.02,173.99) v1(33.02,171.45) v1(33.03,149.76) v1(33.07,107.35) v1(33.1,90.57) v1(33.19,148.07) v1(33.2,146.85) v1(33.31,46.16) v1(33.46,95.65) v1(34.19,72.72) v1(34.32,100.36) v1(34.37,92.33) v1(34.63,89.76) v1(34.64,84.25) v1(34.64,83.12) v1(34.64,81.97) v1(34.64,80.82) v1(34.64,79.67) v1(34.75,97.79) v1(34.75,96.09) v1(34.81,78.2) v1(34.9,52.14) v1(35.27,84.78) v1(35.31,71.55) v1(35.8,47.28) v1(36.01,102.25) v1(35.99,98.12) v1(35.96,78.2) v1(36.25,84.81) v1(36.71,99.54) v1(36.83,173.99) v1(36.83,171.45) v1(36.86,95.76) v1(37.11,78.2) v1(37.4,84.81) v1(37.41,19.2) v1(37.9,91.72) v1(37.98,92.73) v1(38.13,103.73) v1(38.08,100.18) v1(38.18,97.23) v1(38.26,78.2) v1(38.28,72.54) v1(38.42,47.71) v1(38.55,84.86) v1(38.67,96.45) v1(38.79,101.57) v1(38.96,72.49) v1(39.32,71.35) v1(39.41,78.2) v1(39.5,19.66) v1(39.7,84.86) v1(39.78,98.91) v1(39.96,97.85) v1(40.24,93.16) v1(40.32,94.95) v1(40.29,51.99) v1(40.54,104.32) v1(40.64,173.99) v1(40.64,171.45) v1(40.56,78.2) v1(40.82,72.14) v1(40.79,71.35) v1(41,102.22) v1(41.05,74.3) v1(41.12,79.2) v1(41.15,100.02) v1(41.22,84.83) v1(41.2,83.87) v1(41.17,82.68) v1(41.17,81.5) v1(41.17,80.35) v1(41.33,145.54) v1(41.33,143.74) v1(41.31,99.19) v1(41.38,144.63) v1(41.53,96.43) v1(41.91,105.41) v1(41.96,19.69) v1(42.24,96.51) v1(42.34,89.61) v1(42.27,73.03) v1(42.57,87.12) v1(42.89,100.26) v1(42.87,97.78) v1(43.06,91.94) v1(43.31,176.02) v1(43.6,97.83) v1(43.79,20.04) v1(43.87,87.15) v1(44.1,95.45) v1(44.27,104.29) v1(44.71,98.28) v1(44.68,66.52) v1(44.79,100.39) v1(44.88,52.07) v1(44.88,21.16) v1(45.21,92.61) v1(45.72,105.41) v1(45.72,12.7) v1(45.72,10.16) v1(45.85,176.02) v1(45.86,96.18) v1(46.38,85.96) v1(46.43,73.91) v1(46.45,72.45) v1(46.63,119.08) v1(46.57,90.78) v1(46.69,100.39) v1(46.98,87.76) v1(46.99,11.43) v1(47.22,76.77) v1(47.38,92.74) v1(47.47,76.03) v1(47.73,72.83) v1(48.03,119.53) v1(47.98,104.37) v1(47.99,98.32) v1(47.97,82.61) v1(48.06,93.15) v1(48.35,70.57) v1(48.47,88.95) v1(48.55,82.06) v1(48.5,50.53) v1(48.6,100.39) v1(48.58,52.18) v1(49.53,134.62) v1(49.79,94.58) v1(50.01,62.41) v1(50,52.18) v1(50,50.56) v1(50.16,176.53) v1(50.22,86.85) v1(50.38,88.96) v1(50.45,81.89) v1(50.38,76.25) v1(50.5,100.39) v1(50.48,78.33) v1(50.65,85.43) v1(50.8,105.41) v1(50.93,79.78) v1(50.98,104.41) v1(51.01,74.68) v1(51.17,98.29) v1(51.18,83.32) v1(51.17,67.73) v1(51.44,72.09) v1(51.69,94.58) v1(51.69,93.83) v1(52.07,133.35) v1(52.13,86.85) v1(52.28,88.96) v1(52.41,100.39) v1(52.35,81.89) v1(52.45,93.83) v1(52.56,85.43) v1(52.7,176.53) v1(52.7,73.8) v1(52.84,79.78) v1(52.79,70.75) v1(53.09,83.32) v1(53.12,76.22) v1(53.24,98.35) v1(53.34,130.81) v1(53.52,104.41) v1(53.53,67.73) v1(53.6,94.58) v1(53.57,65.88) v1(53.94,100.44) v1(54.03,86.85) v1(53.96,78.15) v1(54.06,72.46) v1(54.14,69.4) v1(54.19,88.96) v1(54.26,81.89) v1(54.46,85.43) v1(54.74,79.73) v1(54.67,74.85) v1(54.95,73.1) v1(54.99,83.32) v1(55.41,71.12) v1(55.5,94.58) v1(55.49,68.05) v1(55.7,98.36) v1(55.88,105.41) v1(55.94,86.85) v1(55.94,71.52) v1(56.06,104.41) v1(56.09,88.96) v1(56.11,81.42) v1(56.22,100.39) v1(56.2,78.51) v1(56.26,93.88) v1(56.39,161.8) v1(56.37,85.35) v1(56.52,163.19) v1(56.5,75.92) v1(56.75,69.77) v1(56.83,66.71) v1(56.87,83) v1(56.86,76.72) v1(57.15,176.66) v1(57.15,173.1) v1(57.15,135.89) v1(57.15,118.11) v1(57.1,93.88) v1(57.28,174.88) v1(57.26,74.86) v1(57.27,70.21) v1(57.41,94.54) v1(57.44,61.39) v1(57.53,80.16) v1(57.59,72.87) v1(57.84,86.85) v1(58,88.96) v1(58.12,100.39) v1(58.1,68.42) v1(58.16,84.7) v1(58.18,65.36) v1(58.33,81.77) v1(58.42,133.35) v1(58.42,128.27) v1(58.42,113.03) v1(58.42,73.35) v1(58.62,68.87) v1(58.77,78.71) v1(58.99,79.99) v1(58.98,76.82) v1(59.06,96.21) v1(59.1,71.33) v1(59.3,78.11) v1(59.36,85.7) v1(59.45,67.08) v1(59.53,64.01) v1(59.61,83.48) v1(59.69,176.66) v1(59.69,173.1) v1(59.69,135.89) v1(59.69,129.54) v1(59.69,127) v1(59.69,115.57) v1(59.7,75.06) v1(59.82,174.88) v1(59.76,88.25) v1(59.77,72) v1(60.03,100.39) v1(59.95,98.28) v1(59.96,67.52) v1(60.2,163.19) v1(60.19,104.41) v1(60.19,76.42) v1(60.32,161.93) v1(60.45,69.98) v1(60.53,84.19) v1(60.56,82.29) v1(60.67,52.18) v1(60.76,92.86) v1(60.79,65.73) v1(60.88,95.48) v1(60.87,62.67) v1(61,80.43) v1(61.05,73.71) v1(61.12,86.91) v1(61.12,70.66) v1(61.31,66.17) v1(61.49,75.03) v1(61.84,98.04) v1(61.79,68.64) v1(61.92,100.21) v1(61.95,78.78) v1(62.11,91.52) v1(62.14,64.38) v1(62.22,61.32) v1(62.35,94.26) v1(62.33,85.44) v1(62.3,50.58) v1(62.4,72.36) v1(62.47,69.31) v1(62.64,83.56) v1(62.56,76.94) v1(62.71,94.73) v1(62.66,64.82) v1(62.81,81.66) v1(62.84,73.68) v1(62.86,141.42) v1(63.14,67.29) v1(63.26,77.4) v1(63.5,113.03) v1(63.48,97.06) v1(63.46,90.17) v1(63.49,63.03) v1(63.57,59.97) v1(63.69,99.5) v1(63.7,92.91) v1(63.69,79.97) v1(63.74,71.01) v1(63.81,67.96) v1(63.91,75.59) v1(64.03,151.28) v1(64,104.41) v1(64.01,63.48) v1(64.08,96.34) v1(64.11,93.44) v1(64.17,100.45) v1(64.18,72.34) v1(64.39,176.66) v1(64.39,175.39) v1(64.49,65.94) v1(64.61,76.05) v1(64.75,88.77) v1(64.83,61.69) v1(64.91,58.62) v1(65.04,91.57) v1(64.99,86.88) v1(64.99,84.98) v1(64.99,83.07) v1(64.99,81.17) v1(65.03,78.61) v1(65.09,69.67) v1(65.2,139.81) v1(65.2,98.33) v1(65.16,66.61) v1(65.29,79.29) v1(65.26,74.25) v1(65.35,62.13) v1(65.49,95.05) v1(65.46,92.09) v1(65.53,70.99) v1(65.61,152.04) v1(65.61,151.31) v1(65.64,53.68) v1(65.79,100.4) v1(65.83,64.59) v1(65.94,157.78) v1(65.94,157.12) v1(66.04,115.57) v1(65.95,74.7) v1(66.13,47.94) v1(66.18,60.34) v1(66.35,90.18) v1(66.31,57.32) v1(66.37,77.27) v1(66.44,68.32) v1(66.54,96.98) v1(66.51,65.27) v1(66.63,104.39) v1(66.6,72.9) v1(66.7,60.78) v1(66.83,93.7) v1(66.79,90.74) v1(66.79,52.13) v1(66.93,176.66) v1(66.93,175.39) v1(66.88,69.64) v1(67.06,88.41) v1(67.1,86.51) v1(67.1,84.6) v1(67.1,82.7) v1(67.1,80.79) v1(67.18,63.25) v1(67.3,73.36) v1(67.38,99.81) v1(67.56,59.03) v1(67.7,83.25) v1(67.72,75.92) v1(67.78,66.97) v1(67.77,56.11) v1(67.89,95.64) v1(67.85,63.92) v1(67.95,71.55) v1(68.05,59.44) v1(68.25,176.73) v1(68.25,175.97) v1(68.2,101.92) v1(68.18,92.35) v1(68.23,79.26) v1(68.23,68.3) v1(68.26,77.11) v1(68.37,48.8) v1(68.53,61.9) v1(68.65,72.01) v1(68.8,155.54) v1(68.8,154.24) v1(68.8,152.94) v1(68.8,151.64) v1(68.8,150.34) v1(68.8,147.74) v1(68.83,145.8) v1(68.95,81.82) v1(69.03,57.81) v1(69.07,74.57) v1(69.13,65.63) v1(69.24,94.29) v1(69.21,90.75) v1(69.2,62.57) v1(69.3,70.21) v1(69.31,54.98) v1(69.37,132.87) v1(69.38,97.91) v1(69.59,88.88) v1(69.59,86.98) v1(69.59,85.07) v1(69.57,66.95) v1(69.75,167.18) v1(69.75,166.37) v1(69.67,161.75) v1(69.67,160.48) v1(69.77,176.73) v1(69.77,175.97) v1(69.82,25.68) v1(69.85,163.83) v1(69.88,60.55) v1(70,101.23) v1(69.99,70.66) v1(70.1,155.54) v1(70.1,154.24) v1(70.1,152.94) v1(70.1,151.64) v1(70.1,150.34) v1(70.1,149.04) v1(70.1,147.74) v1(70.07,96.4) v1(70.11,89.81) v1(70.13,79.21) v1(70.17,77.1) v1(70.32,87.91) v1(70.36,145.8) v1(70.44,104.39) v1(70.37,99.91) v1(70.41,73.22) v1(70.42,48.83) v1(70.48,64.28) v1(70.55,61.23) v1(70.62,94.12) v1(70.58,92.94) v1(70.64,68.86) v1(70.56,56.68) v1(70.72,83.54) v1(70.82,81.43) v1(70.94,86.11) v1(70.92,65.6) v1(70.9,53.94) v1(71.12,113.03) v1(71.2,161.75) v1(71.2,160.48) v1(71.3,176.73) v1(71.3,175.97) v1(71.34,69.31) v1(71.4,155.54) v1(71.4,154.24) v1(71.4,152.94) v1(71.4,151.64) v1(71.4,150.34) v1(71.4,149.04) v1(71.4,147.74) v1(71.6,166.32) v1(71.72,98.6) v1(71.72,91.41) v1(71.76,71.88) v1(71.82,62.93) v1(71.88,145.8) v1(71.91,133.35) v1(71.89,59.88) v1(72.04,79.21) v1(71.99,67.51) v1(71.99,58.58) v1(72.1,97.06) v1(72.07,77.1) v1(72.07,52.18) v1(72.16,55.64) v1(72.33,89.61) v1(72.27,64.25) v1(72.39,115.57) v1(72.52,95.25) v1(72.46,87.71) v1(72.53,85.06) v1(72.58,92.94) v1(72.63,83.54) v1(72.56,52.99) v1(72.63,48.83) v1(72.72,161.75) v1(72.72,160.48) v1(72.72,81.43) v1(72.82,176.73) v1(72.82,175.97) v1(73.03,68.43) v1(73.13,166.32) v1(73.21,70.64) v1(73.17,61.59) v1(73.24,58.53) v1(73.34,66.17) v1(73.41,145.8) v1(73.43,133.27) v1(73.51,174.83) v1(73.51,174.07) v1(73.61,62.91) v1(73.57,48.83) v1(73.66,143.51) v1(73.66,140.97) v1(73.79,104.32) v1(73.82,54.71) v1(73.91,101.94) v1(73.89,95) v1(73.94,79.21) v1(73.98,77.1) v1(74.24,161.75) v1(74.24,160.48) v1(74.35,176.73) v1(74.35,175.97) v1(74.25,87.06) v1(74.26,52.15) v1(74.43,84.95) v1(74.53,83.54) v1(74.52,60.24) v1(74.63,147.07) v1(74.63,81.43) v1(74.65,166.32) v1(74.69,64.82) v1(74.75,57.37) v1(74.93,163.83) v1(74.93,145.8) v1(74.93,138.43) v1(74.92,68.17) v1(75.01,61.61) v1(75.11,133.15) v1(75.08,70.28) v1(75.26,172.25) v1(75.27,170.4) v1(75.44,92.88) v1(75.49,94.99) v1(75.54,53.88) v1(75.62,174.68) v1(75.62,173.91) v1(75.62,147.02) v1(75.56,112.52) v1(75.66,48.83) v1(75.76,171.32) v1(75.77,161.75) v1(75.77,160.48) v1(75.85,79.21) v1(75.79,30.89) v1(75.88,77.1) v1(76,146.35) v1(76,145.54) v1(76.04,63.48) v1(76.02,59.07) v1(76.02,51.4) v1(76.2,168.26) v1(76.17,166.32) v1(76.2,144.78) v1(76.16,87.06) v1(76.34,84.95) v1(76.38,172.27) v1(76.38,170.38) v1(76.44,83.54) v1(76.53,81.43) v1(76.83,112.52) v1(76.82,68.17) v1(77.01,158.47) v1(76.98,70.28) v1(77.17,60.96) v1(77.29,161.75) v1(77.29,160.48) v1(77.3,53.17) v1(77.6,104.32) v1(77.58,95.01) v1(77.7,168.86) v1(77.7,167.59) v1(77.7,166.32) v1(77.75,79.21) v1(77.79,77.1) v1(77.9,63.07) v1(77.86,58.55) v1(78.01,92.9) v1(78.06,87.07) v1(78.1,30.78) v1(78.16,133.12) v1(78.24,84.96) v1(78.34,83.54) v1(78.27,56.42) v1(78.44,81.43) v1(78.54,158.5) v1(78.73,68.17) v1(78.82,161.75) v1(78.82,160.48) v1(78.89,70.28) v1(79.02,168.71) v1(79.01,88.71) v1(79.1,167.59) v1(79.1,166.32) v1(79.07,60.96) v1(79.11,52.56) v1(79.34,102.08) v1(79.38,90.58) v1(79.41,53.37) v1(79.7,95.58) v1(79.66,79.21) v1(79.69,77.1) v1(79.8,63.07) v1(79.76,58.53) v1(80.01,163.83) v1(80.01,144.78) v1(80,85.69) v1(80.25,83.56) v1(80.18,56.42) v1(80.34,81.44) v1(80.42,92.18) v1(80.53,93.56) v1(80.49,30.78) v1(80.61,176.71) v1(80.62,168.86) v1(80.62,167.59) v1(80.62,166.32) v1(80.63,68.17) v1(80.79,70.28) v1(80.95,52.06) v1(81.02,87.3) v1(80.98,60.96) v1(81.17,89.2) v1(81.24,85.18) v1(81.41,104.32) v1(81.36,97.28) v1(81.56,79.21) v1(81.6,77.1) v1(81.62,55.4) v1(81.62,53.29) v1(81.74,88.93) v1(81.71,63.07) v1(81.67,58.53) v1(81.77,93.53) v1(82.14,168.86) v1(82.14,167.59) v1(82.14,166.32) v1(82.09,90.87) v1(82.12,82.14) v1(82.08,56.42) v1(82.19,95.14) v1(82.54,68.17) v1(82.55,138.43) v1(82.7,70.28) v1(82.81,51.68) v1(82.91,90.43) v1(82.88,60.96) v1(83.13,94.86) v1(83.2,83.71) v1(83.35,85.61) v1(83.31,81.93) v1(83.28,80.03) v1(83.37,99.22) v1(83.44,92.21) v1(83.45,87.51) v1(83.49,77.35) v1(83.61,63.07) v1(83.57,58.53) v1(83.67,168.86) v1(83.67,167.59) v1(83.67,166.32) v1(83.7,55.4) v1(83.7,53.29) v1(83.82,163.83) v1(83.82,144.78) v1(83.8,96.7) v1(83.99,56.42) v1(84.4,102.21) v1(84.41,85.49) v1(84.44,68.17) v1(84.45,104.99) v1(84.52,91.45) v1(84.57,100.45) v1(84.56,89.06) v1(84.6,70.28) v1(84.69,95.96) v1(84.7,51.42) v1(84.82,93.53) v1(84.79,60.96) v1(84.94,78.58) v1(85.09,142.24) v1(85.19,168.86) v1(85.19,167.59) v1(85.19,166.32) v1(85.26,98.02) v1(85.42,82.33) v1(85.42,80.42) v1(85.52,63.13) v1(85.48,58.53) v1(85.8,86.49) v1(85.8,83.87) v1(85.79,55.4) v1(85.79,53.29) v1(85.89,56.44) v1(87.5,166.24) v1(87.63,171.45) v1(87.63,168.91) v1(87.63,144.78) v1(87.63,138.43) v1(88.24,89.77) v1(88.16,71.56) v1(88.34,96.95) v1(88.34,94.84) v1(88.29,91.88) v1(88.34,84.71) v1(88.41,107.08) v1(88.38,104.82) v1(88.43,102.11) v1(88.37,99.95) v1(88.37,86.82) v1(88.4,65.62) v1(88.35,56.29) v1(88.35,53.78) v1(88.48,60.85) v1(88.5,51.24) v1(89.01,58.51) v1(89.07,49.13) v1(89.39,63.63) v1(89.9,69.45) v1(90.17,171.45) v1(90.17,168.91) v1(91.44,166.37) v1(93.98,166.37) v1(93.98,129.54) v1(93.98,127) v1(96.52,166.37) v1(97.59,156.41) v1(97.79,166.37) v1(97.79,152.4) v1(97.79,148.59) v1(97.79,143.51) v1(97.79,139.7) v1(97.79,137.16) v1(97.79,132.08) v1(97.79,129.54) v1(97.79,127) v1(99.03,158.45) v1(99.03,157.33) v1(99.01,156.44) v2(35.3,84.14) v2(35.3,82.84) v2(35.3,81.54) v2(35.3,80.24) v2(35.3,78.94) v2(36.6,84.14) v2(36.6,82.84) v2(36.6,81.54) v2(36.6,80.24) v2(36.6,78.94) v2(37.9,84.14) v2(37.9,82.84) v2(37.9,81.54) v2(37.9,80.24) v2(37.9,78.94) v2(39.2,84.14) v2(39.2,82.84) v2(39.2,81.54) v2(39.2,80.24) v2(39.2,78.94) v2(40.5,84.14) v2(40.5,82.84) v2(40.5,81.54) v2(40.5,80.24) v2(40.5,78.94)
